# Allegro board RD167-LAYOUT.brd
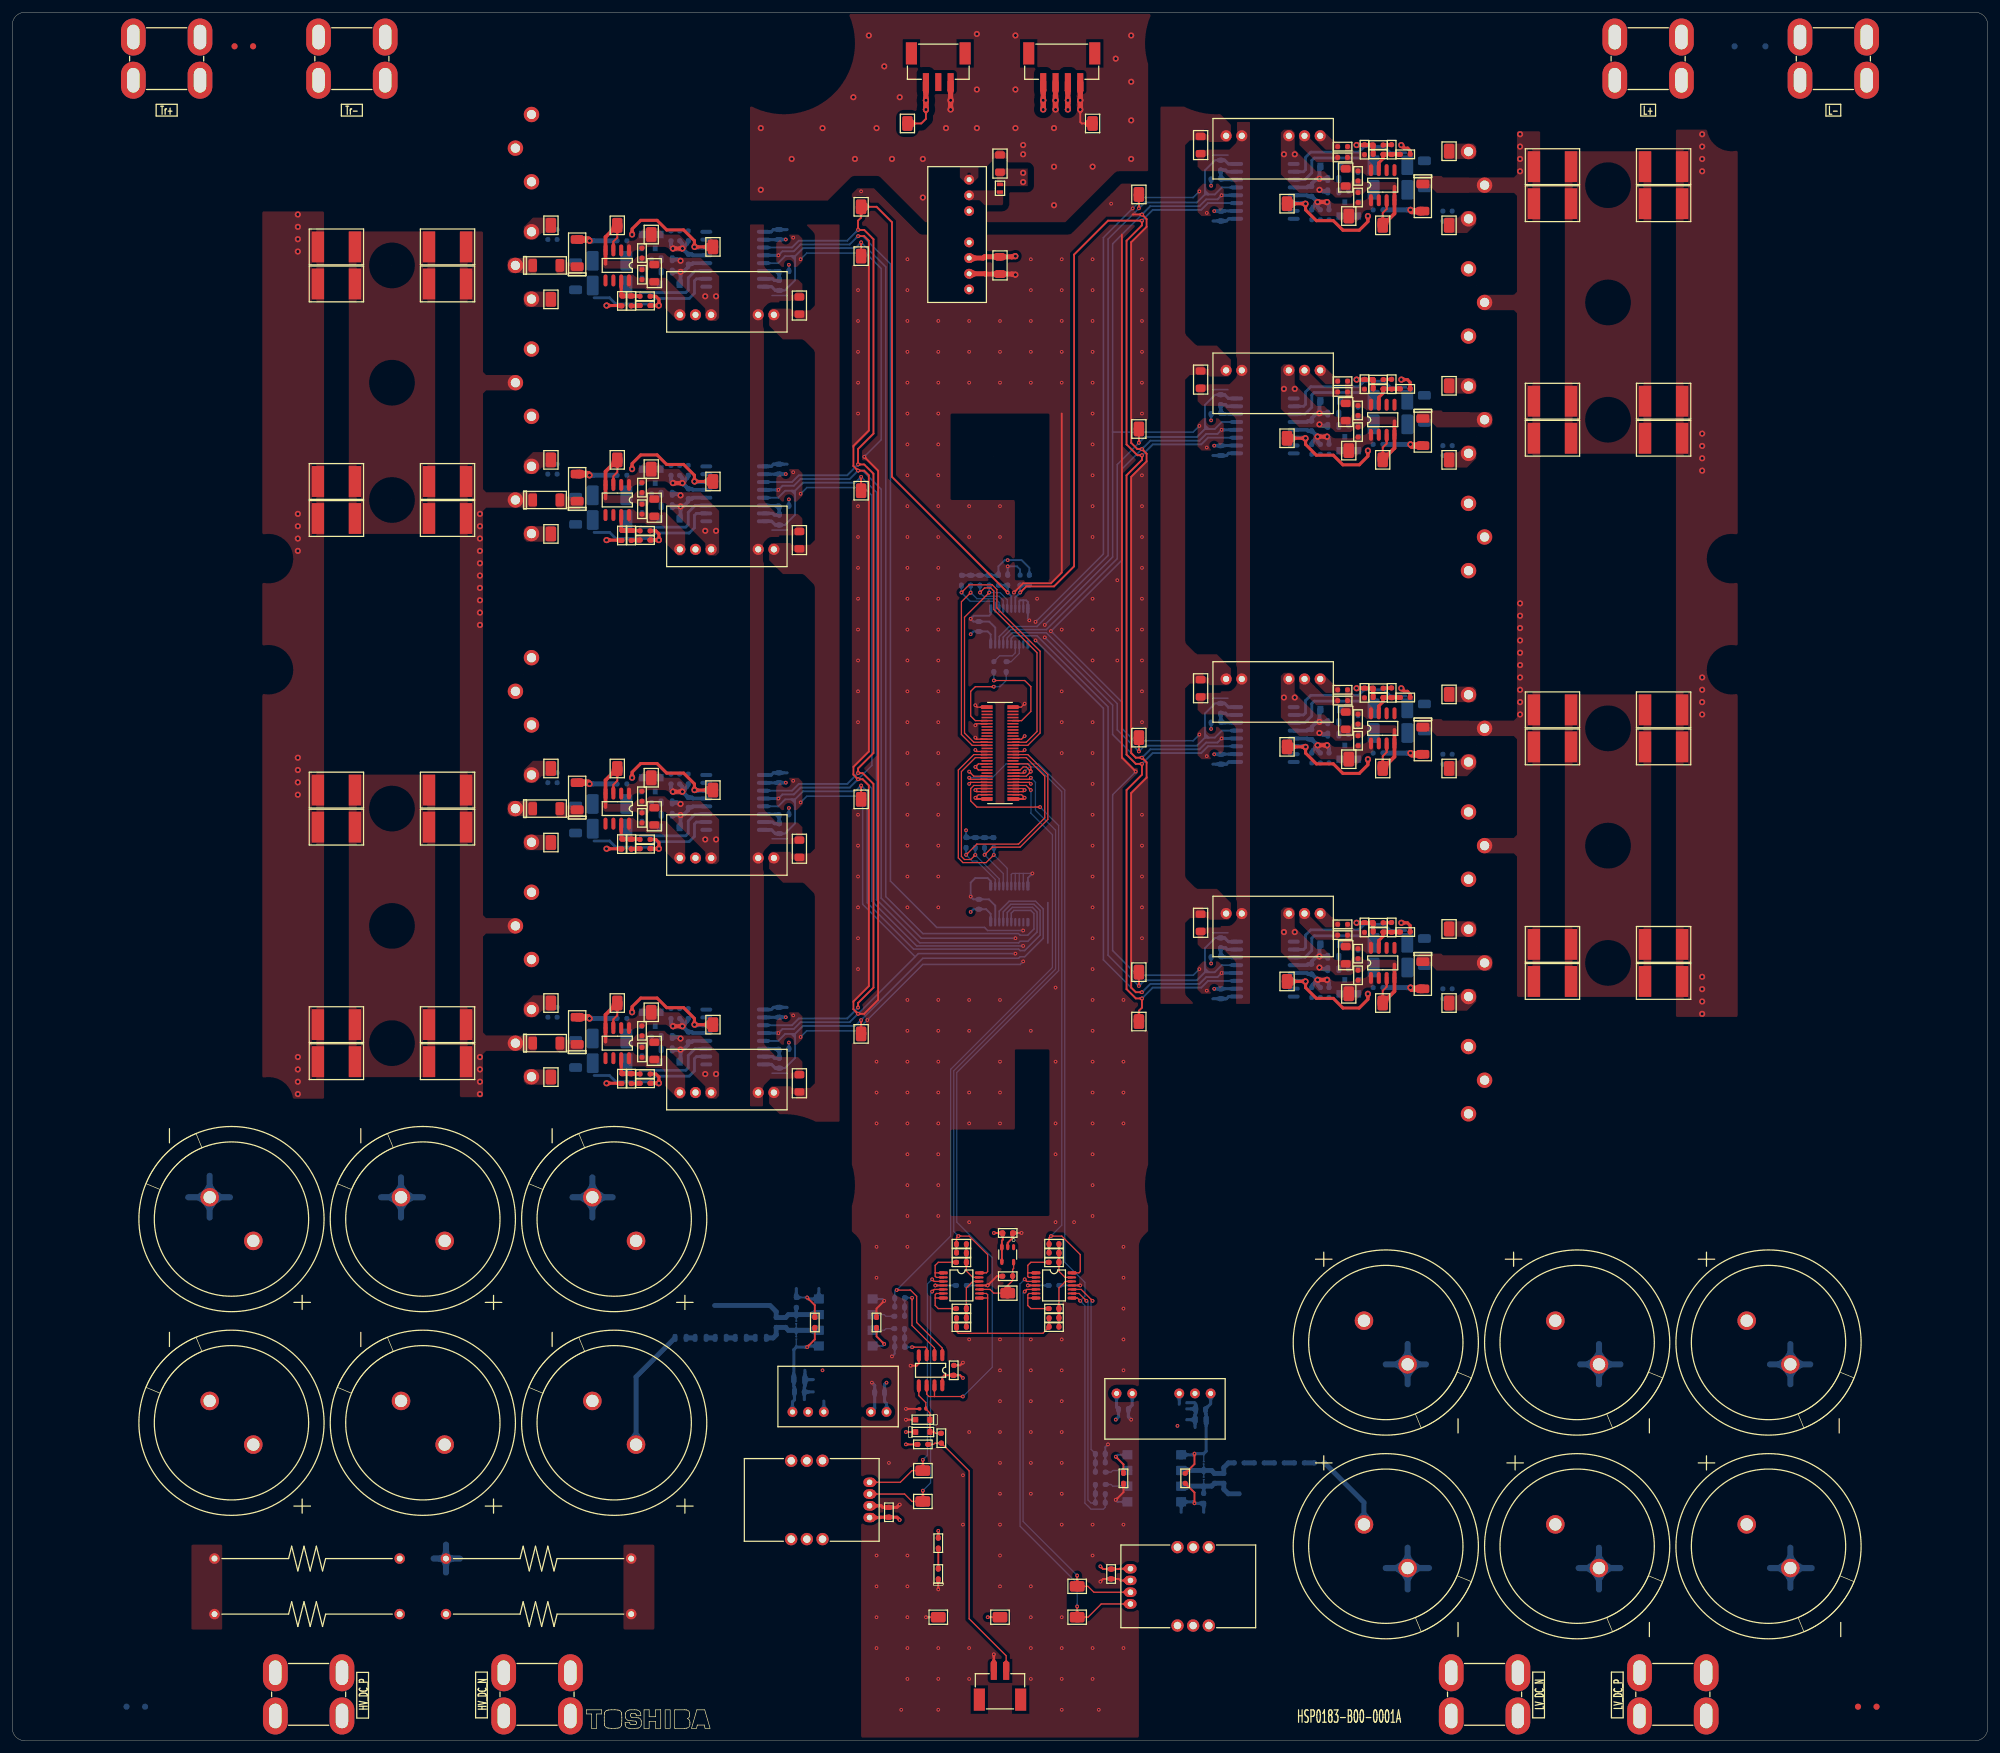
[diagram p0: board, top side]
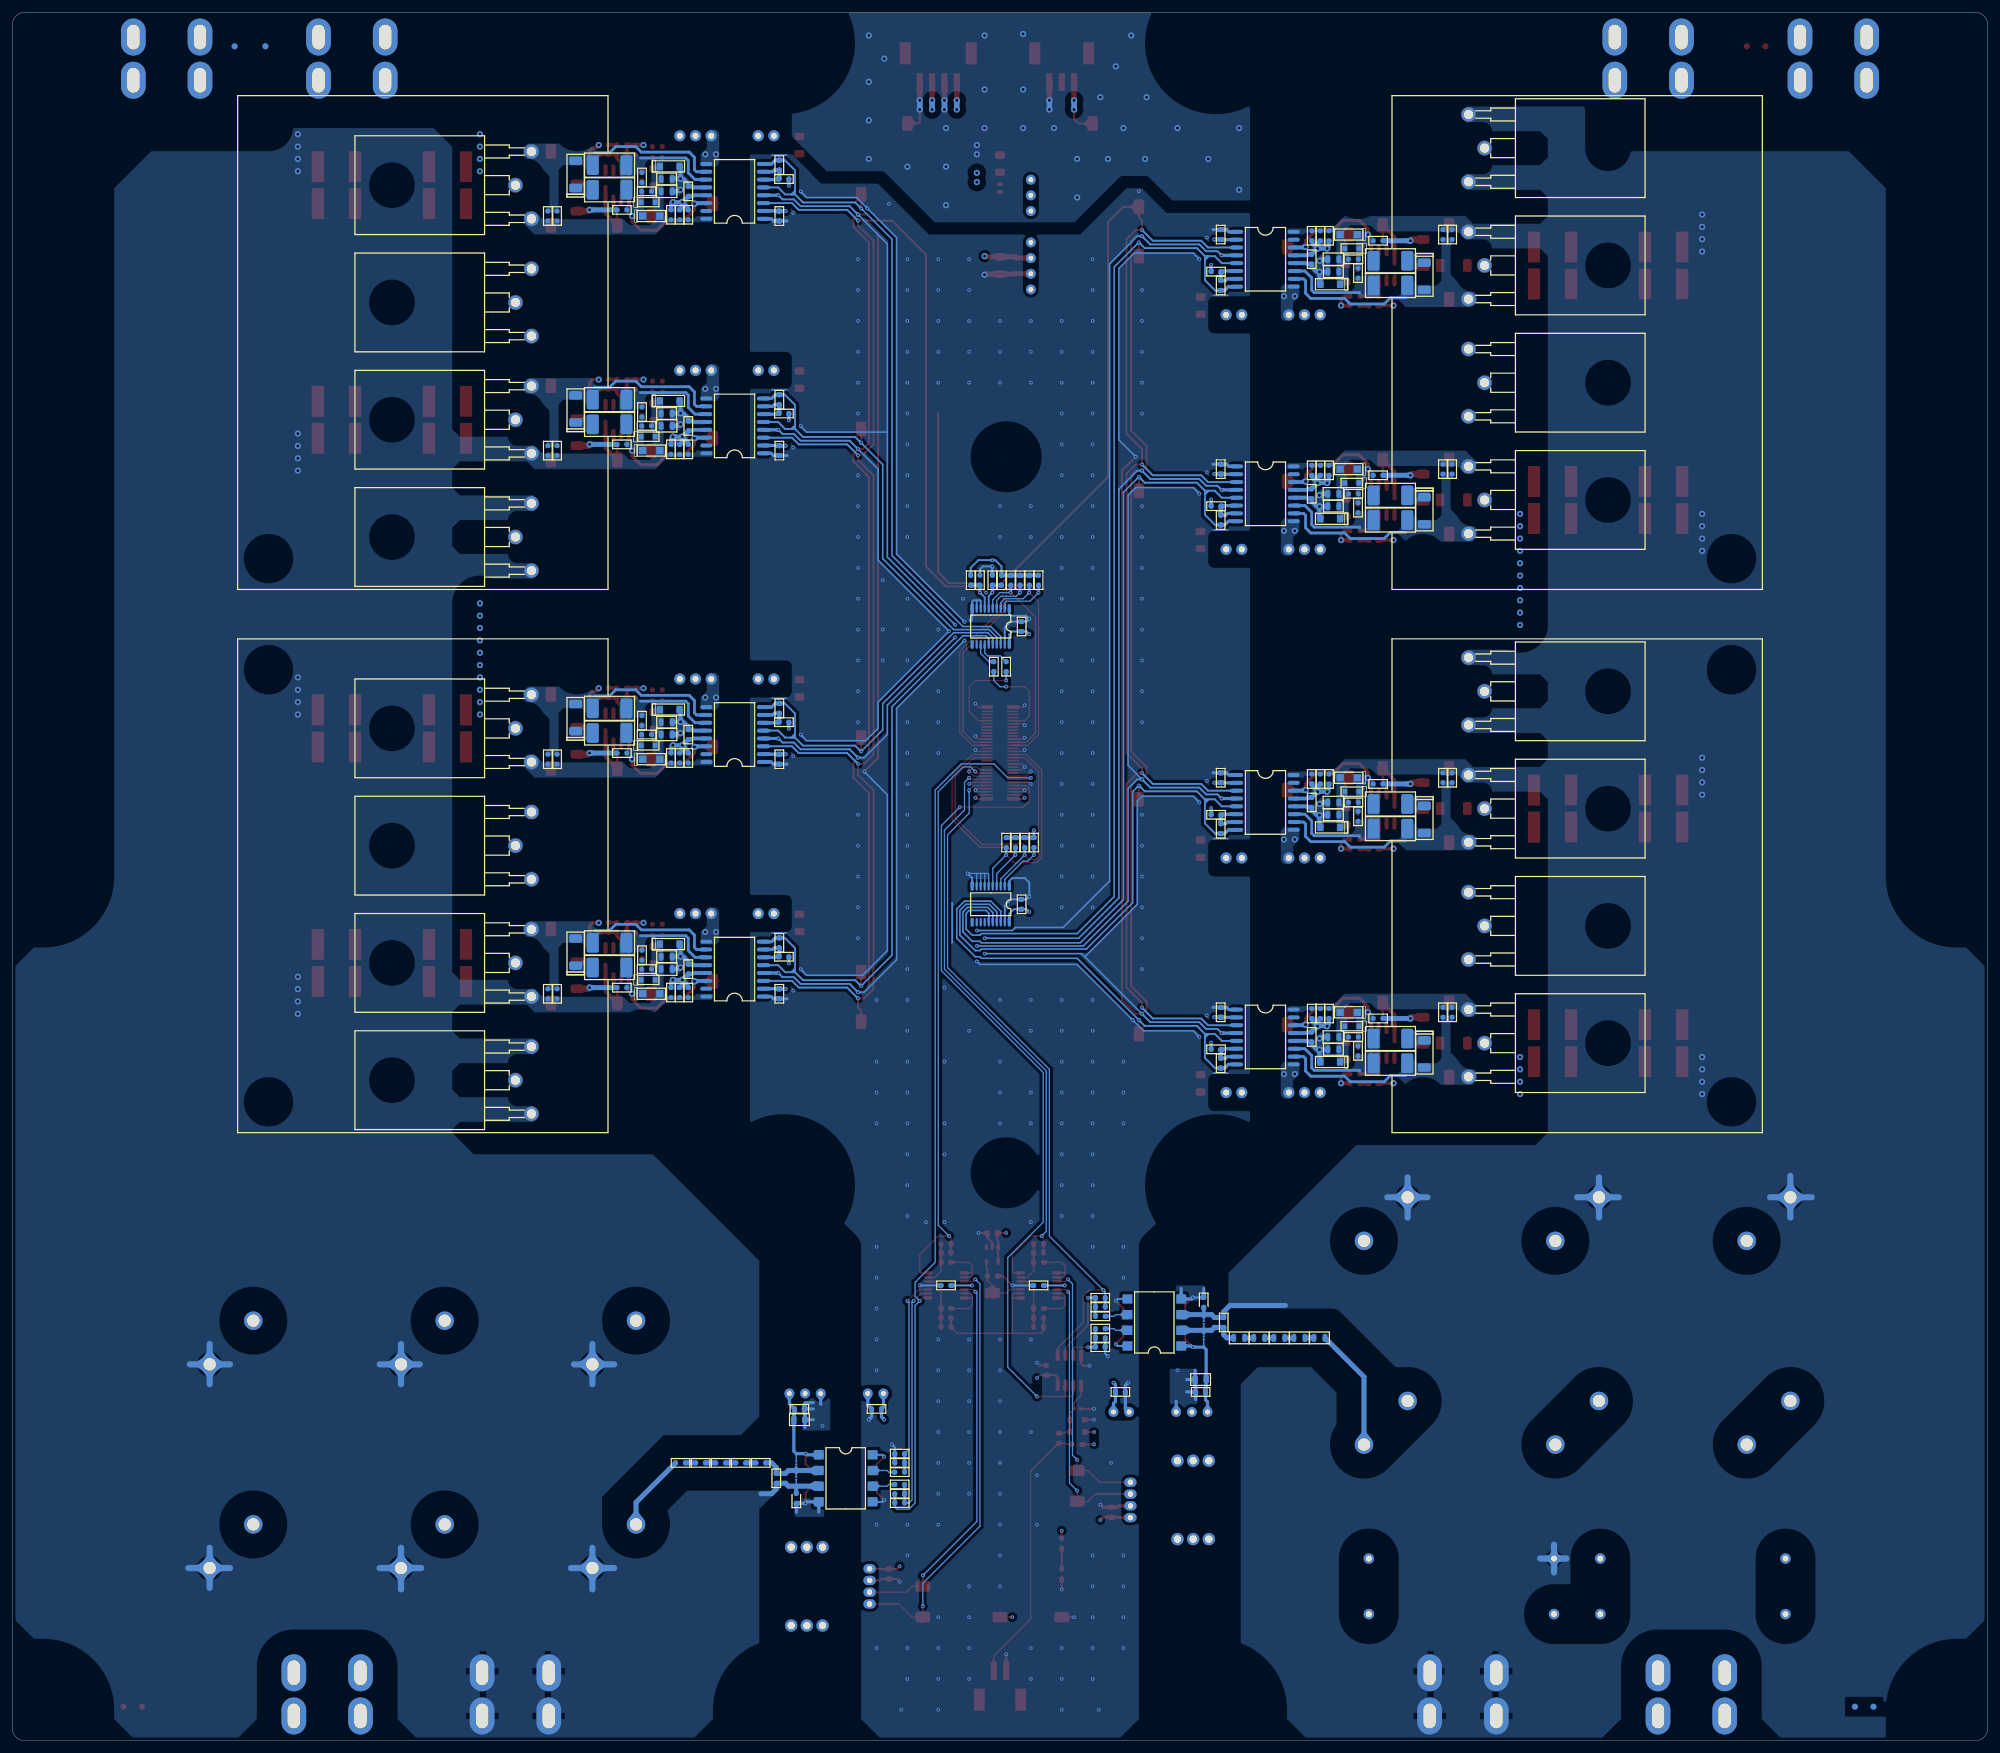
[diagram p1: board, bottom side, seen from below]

Outline 320 x 280 mm; copper layers: TOP, CONDUCTIVE2, CONDUCTIVE3, CONDUCTIVE4, CONDUCTIVE5, BOTTOM. Coordinates in mm from the lower left corner of the outline.
Outline path: 0,278 0.03,278.35 0.12,278.68 0.27,279 0.47,279.29 0.71,279.53 1,279.73 1.32,279.88 1.65,279.97 2,280 318,280 318.35,279.97 318.68,279.88 319,279.73 319.29,279.53 319.53,279.29 319.73,279 319.88,278.68 319.97,278.35 320,278 320,2 319.97,1.65 319.88,1.32 319.73,1 319.53,0.71 319.29,0.47 319,0.27 318.68,0.12 318.35,0.03 318,0 2,0 1.65,0.03 1.32,0.12 1,0.27 0.71,0.47 0.47,0.71 0.27,1 0.12,1.32 0.03,1.65 0,2 0,278

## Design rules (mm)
constraint set DEFAULT: 

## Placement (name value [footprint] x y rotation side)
C1  -  [C_S_1608]  142 37 90 top
C2  -  [C_D_ESMR_VS_30_0X40__1]  35.5 51.5 90 top
C3  -  [C_D_ESMR_VS_30_0X40__1]  66.5 51.5 90 top
C4  -  [C_D_ESMR_VS_30_0X40__1]  97.5 51.5 90 top
C5  -  [C_D_ESMR_VS_30_0X40__1]  35.5 84.5 90 top
C6  -  [C_D_ESMR_VS_30_0X40__1]  66.5 84.5 90 top
C7  -  [C_D_ESMR_VS_30_0X40__1]  97.5 84.5 90 top
C8  -  [C_S_1005]  147.5 53.75 180 top
C10  -  [C_S_1608]  140 67.75 90 top
C11  -  [C_S_1608]  130 67.75 90 top
C12  -  [C_S_1608]  143.75 63.75 0 bottom
C13  -  [C_S_1608]  153.75 73.75 0 bottom
C14  -  [C_S_1608]  125.25 67.75 90 bottom
C15  -  [C_S_1608]  143.75 71.75 0 bottom
C16  -  [C_S_1608]  127.5 56.5 0 bottom
C17  -  [C_S_1608]  140.5 56.5 180 bottom
C18  -  [C_S_1608]  102 115 270 top
C19  -  [C_S_1608]  102.5 108 180 top
C20  -  [C_S_1608]  102 111.5 90 top
C21  -  [C_S_3216_T1_8]  104 111.75 90 top
C22  -  [C_S_3216_T1_8]  127.5 106.5 90 top
C23  -  [C_S_1608]  109.5 117.8 90 bottom
C24  -  [C_S_1608]  109.5 114 270 bottom
C25  -  [C_S_1608]  124.25 118 90 bottom
C26  -  [C_S_1608]  86.75 118 90 bottom
C27  -  [C_S_1608]  102.75 114 0 bottom
C28  -  [C_S_CKG57_6050]  70.5 110 180 top
C29  -  [C_S_CKG57_6050]  70.5 116 180 top
C31  -  [C_S_2012]  106 114 0 bottom
C32  -  [C_S_CKG57_6050]  70.5 148 180 top
C33  -  [C_S_CKG57_6050]  70.5 154 180 top
C34  -  [C_S_CKG57_6050]  52.5 110 180 top
C35  -  [C_S_CKG57_6050]  52.5 116 180 top
C36  -  [C_S_CKG57_6050]  52.5 148 180 top
C37  -  [C_S_CKG57_6050]  52.5 154 180 top
C38  -  [C_S_1608]  102 153 270 top
C39  -  [C_S_1608]  102.5 146 180 top
C40  -  [C_S_1608]  102 149.5 90 top
C41  -  [C_S_3216_T1_8]  104 149.75 90 top
C42  -  [C_S_3216_T1_8]  127.5 144.5 90 top
C43  -  [C_S_1608]  109.5 155.8 90 bottom
C44  -  [C_S_1608]  109.5 152 270 bottom
C45  -  [C_S_1608]  124.25 156 90 bottom
C46  -  [C_S_1608]  86.75 156 90 bottom
C47  -  [C_S_1608]  102.75 152 0 bottom
C49  -  [C_S_2012]  106 152 0 bottom
C50  -  [C_S_1608]  102 203 270 top
C51  -  [C_S_1608]  102.5 196 180 top
C52  -  [C_S_1608]  102 199.5 90 top
C53  -  [C_S_3216_T1_8]  104 199.75 90 top
C54  -  [C_S_3216_T1_8]  127.5 194.5 90 top
C55  -  [C_S_1608]  109.5 205.8 90 bottom
C56  -  [C_S_1608]  109.5 202 270 bottom
C57  -  [C_S_1608]  124.25 206 90 bottom
C58  -  [C_S_1608]  86.75 206 90 bottom
C59  -  [C_S_1608]  102.75 202 0 bottom
C61  -  [C_S_2012]  106 202 0 bottom
C62  -  [C_S_CKG57_6050]  70.5 198 180 top
C63  -  [C_S_CKG57_6050]  70.5 204 180 top
C64  -  [C_S_CKG57_6050]  70.5 236 180 top
C65  -  [C_S_CKG57_6050]  70.5 242 180 top
C66  -  [C_S_CKG57_6050]  52.5 198 180 top
C67  -  [C_S_CKG57_6050]  52.5 204 180 top
C68  -  [C_S_CKG57_6050]  52.5 236 180 top
C69  -  [C_S_CKG57_6050]  52.5 242 180 top
C70  -  [C_S_1608]  102 241 270 top
C71  -  [C_S_1608]  102.5 234 180 top
C72  -  [C_S_1608]  102 237.5 90 top
C73  -  [C_S_3216_T1_8]  104 237.75 90 top
C74  -  [C_S_3216_T1_8]  127.5 232.5 90 top
C75  -  [C_S_1608]  109.5 243.8 90 bottom
C76  -  [C_S_1608]  109.5 240 270 bottom
C77  -  [C_S_1608]  124.25 244 90 bottom
C78  -  [C_S_1608]  86.75 244 90 bottom
C79  -  [C_S_1608]  102.75 240 0 bottom
C81  -  [C_S_2012]  106 240 0 bottom
C82  -  [C_S_3216_T1_8]  192.5 258.5 270 top
C83  -  [C_S_3216_T1_8]  216 253.25 270 top
C84  -  [C_S_1608]  218 253.5 270 top
C85  -  [C_S_1608]  221.25 257 0 top
C86  -  [C_S_1608]  218 250 90 top
C87  -  [C_S_1608]  195.75 247 270 bottom
C88  -  [C_S_1608]  210.5 251 90 bottom
C89  -  [C_S_1608]  210.5 247.2 270 bottom
C90  -  [C_S_1608]  217.25 251 180 bottom
C91  -  [C_S_1608]  233.25 247 270 bottom
C92  -  [C_S_2012]  214 251 180 bottom
C94  -  [C_S_CKG57_6050]  249.5 255 0 top
C95  -  [C_S_CKG57_6050]  249.5 249 0 top
C96  -  [C_S_CKG57_6050]  249.5 217 0 top
C97  -  [C_S_CKG57_6050]  249.5 211 0 top
C98  -  [C_S_CKG57_6050]  267.5 255 0 top
C99  -  [C_S_CKG57_6050]  267.5 249 0 top
C100  -  [C_S_CKG57_6050]  267.5 217 0 top
C101  -  [C_S_CKG57_6050]  267.5 211 0 top
C102  -  [C_S_3216_T1_8]  192.5 220.5 270 top
C103  -  [C_S_3216_T1_8]  216 215.25 270 top
C104  -  [C_S_1608]  218 215.5 270 top
C105  -  [C_S_1608]  221.25 219 0 top
C106  -  [C_S_1608]  218 212 90 top
C107  -  [C_S_1608]  195.75 209 270 bottom
C108  -  [C_S_1608]  210.5 213 90 bottom
C109  -  [C_S_1608]  210.5 209.2 270 bottom
C110  -  [C_S_1608]  217.25 213 180 bottom
C111  -  [C_S_1608]  233.25 209 270 bottom
C112  -  [C_S_2012]  214 213 180 bottom
C114  -  [C_S_3216_T1_8]  192.5 170.5 270 top
C115  -  [C_S_3216_T1_8]  216 165.25 270 top
C116  -  [C_S_1608]  218 165.5 270 top
C117  -  [C_S_1608]  221.25 169 0 top
C118  -  [C_S_1608]  218 162 90 top
C119  -  [C_S_1608]  195.75 159 270 bottom
C120  -  [C_S_1608]  210.5 163 90 bottom
C121  -  [C_S_1608]  210.5 159.2 270 bottom
C122  -  [C_S_1608]  217.25 163 180 bottom
C123  -  [C_S_1608]  233.25 159 270 bottom
C124  -  [C_S_2012]  214 163 180 bottom
C126  -  [C_S_CKG57_6050]  249.5 167 0 top
C127  -  [C_S_CKG57_6050]  249.5 161 0 top
C128  -  [C_S_CKG57_6050]  249.5 129 0 top
C129  -  [C_S_CKG57_6050]  249.5 123 0 top
C130  -  [C_S_CKG57_6050]  267.5 167 0 top
C131  -  [C_S_CKG57_6050]  267.5 161 0 top
C132  -  [C_S_CKG57_6050]  267.5 129 0 top
C133  -  [C_S_CKG57_6050]  267.5 123 0 top
C134  -  [C_S_3216_T1_8]  192.5 132.5 270 top
C135  -  [C_S_3216_T1_8]  216 127.25 270 top
C136  -  [C_S_1608]  218 127.5 270 top
C137  -  [C_S_1608]  221.25 131 0 top
C138  -  [C_S_1608]  218 124 90 top
C139  -  [C_S_1608]  195.75 121 270 bottom
C140  -  [C_S_1608]  210.5 125 90 bottom
C141  -  [C_S_1608]  210.5 121.2 270 bottom
C142  -  [C_S_1608]  217.25 125 180 bottom
C143  -  [C_S_1608]  233.25 121 270 bottom
C144  -  [C_S_2012]  214 125 180 bottom
C146  -  [C_S_1608]  178 27 270 top
C147  -  [C_D_ESMR_VS_30_0X40__1]  284.5 64.5 270 top
C148  -  [C_D_ESMR_VS_30_0X40__1]  253.5 64.5 270 top
C149  -  [C_D_ESMR_VS_30_0X40__1]  222.5 64.5 270 top
C150  -  [C_D_ESMR_VS_30_0X40__1]  284.5 31.5 270 top
C151  -  [C_D_ESMR_VS_30_0X40__1]  253.5 31.5 270 top
C152  -  [C_D_ESMR_VS_30_0X40__1]  222.5 31.5 270 top
C153  -  [C_S_1608]  180 42.5 270 top
C154  -  [C_S_1608]  176.25 38.5 180 bottom
C155  -  [C_S_1608]  190 42.5 270 top
C157  -  [C_S_1608]  194.75 42.5 270 bottom
C158  -  [C_S_1608]  152.5 60 90 top
C159  -  [C_S_1608]  176.25 46.5 180 bottom
C160  -  [C_S_1608]  180 53.75 0 bottom
C161  -  [C_S_1608]  192.5 53.75 180 bottom
C162  -  [C_S_3216_T1_8]  160 255.5 90 top
C163  -  [C_S_3216_T1_8]  160 239 270 top
C164  -  [C_S_1608]  156.5 135.5 90 bottom
C165  -  [C_S_1608]  156.5 180.5 90 bottom
C166  -  [C_S_1608]  163.25 188 90 bottom
C167  -  [C_S_1608]  161.25 188 90 bottom
C168  -  [C_S_1608]  153.75 80.5 180 top
C170  -  [C_S_1608]  153.75 67 180 top
C171  -  [C_S_1608]  168.75 80.5 180 top
C172  -  [C_S_1608]  168.75 73.75 0 bottom
C173  -  [C_S_1608]  168.75 67 180 top
C174  -  [C_S_1608]  161.25 82.25 0 top
C175  -  [C_S_1608]  161.25 75.25 180 top
CN1  -  [CN_S_BM02B_PASS_TFT__1]  160 8 0 top
CN2  -  [CN_S_BM03B_PASS_TFT__1]  150 272 180 top
CN3  -  [CN_S_BM04B_PASS_TFT__1]  170 272 180 top
CN4  -  [CN_S_WR_60S_VFH05_N1]  160 160 90 top
CT1  -  [CT_D_F02PXXXS05L]  129.5 39 180 top
CT2  -  [CT_D_F02PXXXS05L]  190.5 25 0 top
D2  -  [D_S_1_1E1A_USC_AK]  147.5 50 180 top
D3  -  [D_S_1_1E1A_USC_AK]  147.5 52 0 top
D5  -  [D_S_SOD_962_SL2_AK]  127 65.25 90 bottom
D6  -  [D_S_SOD_962_SL2_AK]  127 67.75 90 bottom
D7  -  [D_S_M_FLAT_3_4E1A_AK]  86.5 113 180 top
D8  -  [D_S_M_FLAT_3_4E1A_AK]  91.5 115 270 top
D9  -  [D_S_M_FLAT_3_4E1A_AK]  91.25 111.25 90 bottom
D10  -  [D_S_1_1E1A_USC_AK]  103 115.75 180 bottom
D11  -  [D_S_FLAT_3_2A1S]  103.5 118 180 bottom
D12  -  [D_S_SOD_123_PMDU_AK]  106.5 109.95 180 bottom
D13  -  [D_S_M_FLAT_3_4E1A_AK]  86.5 151 180 top
D14  -  [D_S_M_FLAT_3_4E1A_AK]  91.5 153 270 top
D15  -  [D_S_M_FLAT_3_4E1A_AK]  91.25 149.25 90 bottom
D16  -  [D_S_1_1E1A_USC_AK]  103 153.75 180 bottom
D17  -  [D_S_FLAT_3_2A1S]  103.5 156 180 bottom
D18  -  [D_S_SOD_123_PMDU_AK]  106.5 147.95 180 bottom
D19  -  [D_S_M_FLAT_3_4E1A_AK]  86.5 201 180 top
D20  -  [D_S_M_FLAT_3_4E1A_AK]  91.5 203 270 top
D21  -  [D_S_M_FLAT_3_4E1A_AK]  91.25 199.25 90 bottom
D22  -  [D_S_1_1E1A_USC_AK]  103 203.75 180 bottom
D23  -  [D_S_FLAT_3_2A1S]  103.5 206 180 bottom
D24  -  [D_S_SOD_123_PMDU_AK]  106.5 197.95 180 bottom
D25  -  [D_S_M_FLAT_3_4E1A_AK]  86.5 239 180 top
D26  -  [D_S_M_FLAT_3_4E1A_AK]  91.5 241 270 top
D27  -  [D_S_M_FLAT_3_4E1A_AK]  91.25 237.25 90 bottom
D28  -  [D_S_1_1E1A_USC_AK]  103 241.75 180 bottom
D29  -  [D_S_FLAT_3_2A1S]  103.5 244 180 bottom
D30  -  [D_S_SOD_123_PMDU_AK]  106.5 235.95 180 bottom
D31  -  [D_S_M_FLAT_3_4E1A_AK]  228.5 250 90 top
D33  -  [D_S_M_FLAT_3_4E1A_AK]  228.75 253.75 270 bottom
D34  -  [D_S_FLAT_3_2A1S]  216.5 247 0 bottom
D35  -  [D_S_1_1E1A_USC_AK]  217 249.25 0 bottom
D36  -  [D_S_SOD_123_PMDU_AK]  213.5 255.05 0 bottom
D37  -  [D_S_M_FLAT_3_4E1A_AK]  228.5 212 90 top
D39  -  [D_S_M_FLAT_3_4E1A_AK]  228.75 215.75 270 bottom
D40  -  [D_S_FLAT_3_2A1S]  216.5 209 0 bottom
D41  -  [D_S_1_1E1A_USC_AK]  217 211.25 0 bottom
D42  -  [D_S_SOD_123_PMDU_AK]  213.5 217.05 0 bottom
D43  -  [D_S_M_FLAT_3_4E1A_AK]  228.5 162 90 top
D45  -  [D_S_M_FLAT_3_4E1A_AK]  228.75 165.75 270 bottom
D46  -  [D_S_FLAT_3_2A1S]  216.5 159 0 bottom
D47  -  [D_S_1_1E1A_USC_AK]  217 161.25 0 bottom
D48  -  [D_S_SOD_123_PMDU_AK]  213.5 167.05 0 bottom
D49  -  [D_S_M_FLAT_3_4E1A_AK]  228.5 124 90 top
D51  -  [D_S_M_FLAT_3_4E1A_AK]  228.75 127.75 270 bottom
D52  -  [D_S_FLAT_3_2A1S]  216.5 121 0 bottom
D53  -  [D_S_1_1E1A_USC_AK]  217 123.25 0 bottom
D54  -  [D_S_SOD_123_PMDU_AK]  213.5 129.05 0 bottom
D56  -  [D_S_SOD_962_SL2_AK]  193 45 270 bottom
D58  -  [D_S_SOD_962_SL2_AK]  193 42.5 270 bottom
D59  -  [D_D_TO_247_3_AK_REVE_1]  81.5 132 270 bottom
D60  -  [D_D_TO_247_3_AK_REVE_1]  81.5 170 270 bottom
D61  -  [D_D_TO_247_3_AK_REVE_1]  81.5 220 270 bottom
D62  -  [D_D_TO_247_3_AK_REVE_1]  81.5 258 270 bottom
D63  -  [D_D_TO_247_3_AK_REVE_1]  238.5 233 90 bottom
D64  -  [D_D_TO_247_3_AK_REVE_1]  238.5 195 90 bottom
D65  -  [D_D_TO_247_3_AK_REVE_1]  238.5 145 90 bottom
D66  -  [D_D_TO_247_3_AK_REVE_1]  238.5 107 90 bottom
IC1  -  [IC_SOP14_0_65_PW]  153.75 73.75 270 top
IC2  -  [IC_SOP8_2_54_11_10C4_1]  135 67.75 90 bottom
IC3  -  [IC_SOP8_1_27_D]  98 113 180 top
IC4  -  [IC_SOP16_1_27_11_10M_1]  117 114 270 bottom
IC5  -  [IC_SOP8_1_27_D]  98 151 180 top
IC6  -  [IC_SOP16_1_27_11_10M_1]  117 152 270 bottom
IC7  -  [IC_SOP8_1_27_D]  98 201 180 top
IC8  -  [IC_SOP16_1_27_11_10M_1]  117 202 270 bottom
IC9  -  [IC_SOP8_1_27_D]  98 239 180 top
IC10  -  [IC_SOP16_1_27_11_10M_1]  117 240 270 bottom
IC11  -  [IC_SOP8_1_27_D]  222 252 0 top
IC12  -  [IC_SOP16_1_27_11_10M_1]  203 251 90 bottom
IC13  -  [IC_SOP8_1_27_D]  222 214 0 top
IC14  -  [IC_SOP16_1_27_11_10M_1]  203 213 90 bottom
IC15  -  [IC_SOP8_1_27_D]  222 164 0 top
IC16  -  [IC_SOP16_1_27_11_10M_1]  203 163 90 bottom
IC17  -  [IC_SOP8_1_27_D]  222 126 0 top
IC18  -  [IC_SOP16_1_27_11_10M_1]  203 125 90 bottom
IC19  -  [IC_SOP8_1_27_D]  148.75 60 180 top
IC20  -  [IC_SOP8_2_54_11_10C4_1]  185 42.5 270 bottom
IC21  -  [IC_SOP20_0_65_FT]  161.5 135.5 0 bottom
IC22  -  [IC_SOP20_0_65_FT]  161.5 180.5 0 bottom
IC23  -  [IC_SOP5_0_95_DDC]  161.25 78.75 90 top
IC24  -  [IC_SOP14_0_65_PW]  168.75 73.75 270 top
L1  -  [L_S_MBKK1608]  160 251.5 270 top
LED1  -  [LED_S_1608_AK]  150 27 270 top
NOREF  -  [unnamed]  41.5 261.5 90 top
NOREF#2  -  [unnamed]  91.5 261.5 90 top
NOREF#3  -  [unnamed]  228.5 261.5 0 top
NOREF#4  -  [unnamed]  41.5 103.5 90 top
NOREF#5  -  [unnamed]  228.5 191.5 0 top
NOREF#6  -  [unnamed]  278.5 191.5 0 top
NOREF#7  -  [#2]  93 2 0 top
NOREF#8  -  [#2]  5 5 0 top
NOREF#9  -  [unnamed#3]  160 170 270 top
NOREF#10  -  [#2]  125 90 0 top
NOREF#11  -  [#2]  195 5 0 top
NOREF#12  -  [unnamed]  91.5 191.5 0 top
NOREF#13  -  [unnamed]  41.5 173.5 0 top
NOREF#14  -  [unnamed]  278.5 261.5 0 top
NOREF#15  -  [unnamed]  91.5 103.5 90 top
NOREF#16  -  [unnamed]  228.5 103.5 270 top
NOREF#17  -  [unnamed]  41.5 191.5 0 top
NOREF#18  -  [#2]  5 140 0 top
NOREF#19  -  [unnamed]  278.5 103.5 270 top
NOREF#20  -  [#2]  125 275 0 top
NOREF#21  -  [#2]  315 275 270 top
NOREF#22  -  [unnamed]  299 5.5 0 top
NOREF#23  -  [unnamed]  91.5 173.5 0 top
NOREF#24  -  [#2]  125 5 0 top
NOREF#25  -  [unnamed]  36 274.5 0 top
NOREF#26  -  [unnamed]  228.5 173.5 0 top
NOREF#27  -  [#2]  315 140 0 top
NOREF#28  -  [#2]  5 275 0 top
NOREF#29  -  [unnamed]  39 274.5 0 top
NOREF#30  -  [#2]  195 90 0 top
NOREF#31  -  [unnamed]  278.5 173.5 0 top
NOREF#32  -  [#2]  195 275 0 top
NOREF#33  -  [unnamed]  302 5.5 0 top
NOREF#34  -  [#2]  315 5 0 top
NOREF#35  -  [unnamed]  21.5 5.5 180 bottom
NOREF#36  -  [unnamed]  284 274.5 90 bottom
NOREF#37  -  [unnamed]  18.5 5.5 180 bottom
NOREF#38  -  [unnamed]  279 274.5 90 bottom
PS1  -  [IC_D_RXXPXX]  134 53.25 180 top
PS2  -  [PS_D_S_2WR2_MORNSUN]  115.75 105 180 top
PS3  -  [PS_D_S_2WR2_MORNSUN]  115.75 143 180 top
PS4  -  [PS_D_S_2WR2_MORNSUN]  115.75 193 180 top
PS5  -  [PS_D_S_2WR2_MORNSUN]  115.75 231 180 top
PS6  -  [PS_D_S_2WR2_MORNSUN]  204.25 260 0 top
PS7  -  [PS_D_S_2WR2_MORNSUN]  204.25 222 0 top
PS8  -  [PS_D_S_2WR2_MORNSUN]  204.25 172 0 top
PS9  -  [PS_D_S_2WR2_MORNSUN]  204.25 134 0 top
PS10  -  [IC_D_RXXPXX]  186.5 56.25 0 top
PS11  -  [IC_D_MGFS10_COSEL]  155 244 270 top
Q1  -  [Q_D_TO_247_3_GDS_SP__1]  81.5 113 270 bottom
Q2  -  [Q_D_TO_247_3_GDS_SP__1]  81.5 151 270 bottom
Q3  -  [Q_D_TO_247_3_GDS_SP__1]  81.5 201 270 bottom
Q4  -  [Q_D_TO_247_3_GDS_SP__1]  81.5 239 270 bottom
Q5  -  [Q_D_TO_247_3_GDS_SP__1]  238.5 252 90 bottom
Q6  -  [Q_D_TO_247_3_GDS_SP__1]  238.5 214 90 bottom
Q7  -  [Q_D_TO_247_3_GDS_SP__1]  238.5 164 90 bottom
Q8  -  [Q_D_TO_247_3_GDS_SP__1]  238.5 126 90 bottom
R1  -  [R_D_ROX5S]  47.75 29.5 180 top
R2  -  [R_D_ROX5S]  47.75 20.5 0 top
R3  -  [R_S_1608]  147.5 48 0 top
R4  -  [R_D_ROX5S]  85.25 20.5 0 top
R5  -  [R_S_1608]  150.5 49 270 top
R7  -  [R_D_ROX5S]  85.25 29.5 180 top
R8  -  [R_S_1608]  143.75 65.25 0 bottom
R9  -  [R_S_1608]  143.75 66.75 0 bottom
R10  -  [R_S_2012]  108.25 65.25 0 bottom
R11  -  [R_S_2012]  111.5 65.25 0 bottom
R12  -  [R_S_2012]  114.75 65.25 0 bottom
R13  -  [R_S_2012]  118 65.25 0 bottom
R14  -  [R_S_2012]  121.25 65.25 0 bottom
R15  -  [R_S_1608]  123.75 67.75 90 bottom
R16  -  [R_S_1608]  143.75 68.75 0 bottom
R17  -  [R_S_1608]  127 71 90 bottom
R18  -  [R_S_1608]  143.75 70.25 0 bottom
R19  -  [R_S_2012]  127.5 58.5 0 bottom
R20  -  [R_S_1608]  100.25 107.25 90 top
R21  -  [R_S_1608]  102.5 106.5 180 top
R22  -  [R_S_1608]  98.75 107.25 270 top
R23  -  [R_S_1608]  125 112 180 bottom
R24  -  [R_S_1608]  98.75 117 180 bottom
R25  -  [R_S_1608]  102 111.75 270 bottom
R26  -  [R_S_6432]  96.75 113.75 0 bottom
R27  -  [R_S_6432]  96.75 109.75 180 bottom
R28  -  [R_S_1608]  124.25 109.75 270 bottom
R29  -  [R_S_1608]  88.25 118 90 bottom
R30  -  [R_S_1608]  108.1 117.8 90 bottom
R31  -  [R_S_1608]  106.7 117.8 90 bottom
R32  -  [R_S_1608]  102.5 144.5 180 top
R33  -  [R_S_1608]  98.75 145.25 270 top
R34  -  [R_S_1608]  100.25 145.25 90 top
R35  -  [R_S_1608]  125 150 180 bottom
R36  -  [R_S_1608]  98.75 155 180 bottom
R37  -  [R_S_1608]  102 149.75 270 bottom
R38  -  [R_S_6432]  96.75 151.75 0 bottom
R39  -  [R_S_6432]  96.75 147.75 180 bottom
R40  -  [R_S_1608]  124.25 147.75 270 bottom
R41  -  [R_S_1608]  88.25 156 90 bottom
R42  -  [R_S_1608]  108.1 155.8 90 bottom
R43  -  [R_S_1608]  106.7 155.8 90 bottom
R44  -  [R_S_1608]  100.25 195.25 90 top
R45  -  [R_S_1608]  102.5 194.5 180 top
R46  -  [R_S_1608]  98.75 195.25 270 top
R47  -  [R_S_1608]  125 200 180 bottom
R48  -  [R_S_1608]  98.75 205 180 bottom
R49  -  [R_S_1608]  102 199.75 270 bottom
R50  -  [R_S_6432]  96.75 201.75 0 bottom
R51  -  [R_S_6432]  96.75 197.75 180 bottom
R52  -  [R_S_1608]  124.25 197.75 270 bottom
R53  -  [R_S_1608]  88.25 206 90 bottom
R54  -  [R_S_1608]  108.1 205.8 90 bottom
R55  -  [R_S_1608]  106.7 205.8 90 bottom
R56  -  [R_S_1608]  100.25 233.25 90 top
R57  -  [R_S_1608]  102.5 232.5 180 top
R58  -  [R_S_1608]  98.75 233.25 270 top
R59  -  [R_S_1608]  125 238 180 bottom
R60  -  [R_S_1608]  98.75 243 180 bottom
R61  -  [R_S_1608]  102 237.75 270 bottom
R62  -  [R_S_6432]  96.75 239.75 0 bottom
R63  -  [R_S_6432]  96.75 235.75 180 bottom
R64  -  [R_S_1608]  124.25 235.75 270 bottom
R65  -  [R_S_1608]  88.25 244 90 bottom
R66  -  [R_S_1608]  108.1 243.8 90 bottom
R67  -  [R_S_1608]  106.7 243.8 90 bottom
R68  -  [R_S_1608]  221.25 258.5 0 top
R69  -  [R_S_1608]  223.45 257.75 270 top
R70  -  [R_S_1608]  225.65 257 0 top
R71  -  [R_S_1608]  195 253 0 bottom
R72  -  [R_S_1608]  221.25 248 180 bottom
R73  -  [R_S_1608]  218 253.25 90 bottom
R74  -  [R_S_6432]  223.25 251.25 180 bottom
R75  -  [R_S_1608]  195.75 255.25 90 bottom
R76  -  [R_S_6432]  223.25 255.25 180 bottom
R77  -  [R_S_1608]  211.9 247.2 270 bottom
R78  -  [R_S_1608]  213.3 247.2 270 bottom
R79  -  [R_S_1608]  231.75 247 270 bottom
R80  -  [R_S_1608]  221.25 220.5 0 top
R81  -  [R_S_1608]  223.45 219.75 270 top
R82  -  [R_S_1608]  225.65 219 0 top
R83  -  [R_S_1608]  195 215 0 bottom
R84  -  [R_S_1608]  221.25 210 180 bottom
R85  -  [R_S_1608]  218 215.25 90 bottom
R86  -  [R_S_6432]  223.25 213.25 180 bottom
R87  -  [R_S_1608]  195.75 217.25 90 bottom
R88  -  [R_S_6432]  223.25 217.25 180 bottom
R89  -  [R_S_1608]  211.9 209.2 270 bottom
R90  -  [R_S_1608]  213.3 209.2 270 bottom
R91  -  [R_S_1608]  231.75 209 270 bottom
R92  -  [R_S_1608]  221.25 170.5 0 top
R93  -  [R_S_1608]  223.45 169.75 270 top
R94  -  [R_S_1608]  225.65 169 0 top
R95  -  [R_S_1608]  195 165 0 bottom
R96  -  [R_S_1608]  221.25 160 180 bottom
R97  -  [R_S_1608]  218 165.25 90 bottom
R98  -  [R_S_6432]  223.25 163.25 180 bottom
R99  -  [R_S_1608]  195.75 167.25 90 bottom
R100  -  [R_S_6432]  223.25 167.25 180 bottom
R101  -  [R_S_1608]  211.9 159.2 270 bottom
R102  -  [R_S_1608]  213.3 159.2 270 bottom
R103  -  [R_S_1608]  231.75 159 270 bottom
R104  -  [R_S_1608]  221.25 132.5 0 top
R105  -  [R_S_1608]  223.45 131.75 270 top
R106  -  [R_S_1608]  225.65 131 0 top
R107  -  [R_S_1608]  195 127 0 bottom
R108  -  [R_S_1608]  221.25 122 180 bottom
R109  -  [R_S_1608]  218 127.25 90 bottom
R110  -  [R_S_6432]  223.25 125.25 180 bottom
R111  -  [R_S_1608]  195.75 129.25 90 bottom
R112  -  [R_S_6432]  223.25 129.25 180 bottom
R113  -  [R_S_1608]  211.9 121.2 270 bottom
R114  -  [R_S_1608]  213.3 121.2 270 bottom
R115  -  [R_S_1608]  231.75 121 270 bottom
R120  -  [R_S_1608]  176.25 40 180 bottom
R122  -  [R_S_1608]  176.25 41.5 180 bottom
R123  -  [R_S_1608]  176.25 43.5 180 bottom
R124  -  [R_S_1608]  198.75 45 180 bottom
R125  -  [R_S_1608]  202 45 180 bottom
R126  -  [R_S_1608]  205.25 45 180 bottom
R127  -  [R_S_1608]  208.5 45 180 bottom
R128  -  [R_S_1608]  211.75 45 180 bottom
R129  -  [R_S_1608]  176.25 45 180 bottom
R130  -  [R_S_1608]  193 39.25 270 bottom
R131  -  [R_S_1608]  196.25 42.5 270 bottom
R132  -  [R_S_2012]  192.5 52 180 bottom
R133  -  [R_S_1608]  150 32 270 top
R134  -  [R_S_1608]  154.5 145.5 270 bottom
R135  -  [R_S_1608]  156 145.5 270 bottom
R136  -  [R_S_1608]  157.5 145.5 270 bottom
R137  -  [R_S_1608]  159 145.5 270 bottom
R138  -  [R_S_1608]  153.75 188 270 bottom
R139  -  [R_S_1608]  155.25 188 270 bottom
R140  -  [R_S_1608]  156.75 188 270 bottom
R141  -  [R_S_1608]  158.25 188 270 bottom
R142  -  [R_S_1608]  159.75 188 270 bottom
R143  -  [R_S_1608]  164.75 188 270 bottom
R144  -  [R_S_1608]  159 174 270 bottom
R145  -  [R_S_1608]  161 174 270 bottom
R153  -  [R_S_1608]  153.75 77.5 180 top
R154  -  [R_S_1608]  153.75 70 180 top
R155  -  [R_S_1608]  153.75 79 0 top
R156  -  [R_S_1608]  153.75 68.5 0 top
R157  -  [R_S_1608]  168.75 77.5 180 top
R158  -  [R_S_1608]  168.75 79 0 top
R159  -  [R_S_1608]  168.75 70 180 top
R160  -  [R_S_1608]  168.75 68.5 0 top
R161  -  [R_S_1608]  219.05 257.75 90 top
R162  -  [R_S_1608]  215.5 258.25 0 top
R163  -  [R_S_1608]  215.5 256.5 0 top
R164  -  [R_S_1608]  219.05 219.75 90 top
R165  -  [R_S_1608]  215.5 220.25 0 top
R166  -  [R_S_1608]  215.5 218.5 0 top
R167  -  [R_S_1608]  219.05 169.75 90 top
R168  -  [R_S_1608]  215.5 170.25 0 top
R169  -  [R_S_1608]  215.5 168.5 0 top
R170  -  [R_S_1608]  219.05 131.75 90 top
R171  -  [R_S_1608]  215.5 132.25 0 top
R172  -  [R_S_1608]  215.5 130.5 0 top
R173  -  [R_S_2012]  106 112 0 bottom
R174  -  [R_S_2012]  106 150 0 bottom
R175  -  [R_S_2012]  106 200 0 bottom
R176  -  [R_S_2012]  106 238 0 bottom
R177  -  [R_S_2012]  214 253 180 bottom
R178  -  [R_S_2012]  214 215 180 bottom
R179  -  [R_S_2012]  214 165 180 bottom
R180  -  [R_S_2012]  214 127 180 bottom
TB1  -  [TB_D_OP_057]  48 7.5 180 top
TB2  -  [TB_D_OP_057]  85 7.5 180 top
TB3  -  [TB_D_OP_057]  25 272.5 180 top
TB4  -  [TB_D_OP_057]  55 272.5 0 top
TB5  -  [TB_D_OP_057]  265 272.5 0 top
TB6  -  [TB_D_OP_057]  295 272.5 180 top
TB7  -  [TB_D_OP_057]  269 7.5 0 top
TB8  -  [TB_D_OP_057]  238.5 7.5 0 top
TP1  -  [TP_HK_3_G]  147.5 38.75 180 top
TP2  -  [TP_HK_3_G]  103.5 118 90 top
TP3  -  [TP_HK_3_G]  113.5 116 90 top
TP4  -  [TP_HK_3_G]  87.25 107.5 90 top
TP5  -  [TP_HK_3_G]  87.25 119.5 90 top
TP6  -  [TP_HK_3_G]  98 119.5 90 top
TP7  -  [TP_HK_3_G]  103.5 156 90 top
TP8  -  [TP_HK_3_G]  113.5 154 90 top
TP9  -  [TP_HK_3_G]  87.25 145.5 90 top
TP10  -  [TP_HK_3_G]  87.25 157.5 90 top
TP11  -  [TP_HK_3_G]  98 157.5 90 top
TP12  -  [TP_HK_3_G]  103.5 206 90 top
TP13  -  [TP_HK_3_G]  113.5 204 90 top
TP14  -  [TP_HK_3_G]  87.25 195.5 90 top
TP15  -  [TP_HK_3_G]  87.25 207.5 90 top
TP16  -  [TP_HK_3_G]  98 207.5 90 top
TP17  -  [TP_HK_3_G]  103.5 244 90 top
TP18  -  [TP_HK_3_G]  113.5 242 90 top
TP19  -  [TP_HK_3_G]  87.25 233.5 90 top
TP20  -  [TP_HK_3_G]  87.25 245.5 90 top
TP21  -  [TP_HK_3_G]  98 245.5 90 top
TP22  -  [TP_HK_3_G]  216.5 247 270 top
TP23  -  [TP_HK_3_G]  206.5 249 270 top
TP24  -  [TP_HK_3_G]  232.75 257.5 270 top
TP25  -  [TP_HK_3_G]  232.75 245.5 270 top
TP26  -  [TP_HK_3_G]  222 245.5 270 top
TP27  -  [TP_HK_3_G]  216.5 209 270 top
TP28  -  [TP_HK_3_G]  206.5 211 270 top
TP29  -  [TP_HK_3_G]  232.75 219.5 270 top
TP30  -  [TP_HK_3_G]  232.75 207.5 270 top
TP31  -  [TP_HK_3_G]  222 207.5 270 top
TP32  -  [TP_HK_3_G]  216.5 159 270 top
TP33  -  [TP_HK_3_G]  206.5 161 270 top
TP34  -  [TP_HK_3_G]  232.75 169.5 270 top
TP35  -  [TP_HK_3_G]  232.75 157.5 270 top
TP36  -  [TP_HK_3_G]  222 157.5 270 top
TP37  -  [TP_HK_3_G]  216.5 121 270 top
TP38  -  [TP_HK_3_G]  206.5 123 270 top
TP39  -  [TP_HK_3_G]  232.75 131.5 270 top
TP40  -  [TP_HK_3_G]  232.75 119.5 270 top
TP41  -  [TP_HK_3_G]  222 119.5 270 top
TP42  -  [TP_HK_3_G]  172.5 25 0 top
TP43  -  [TP_HK_3_G]  145 262 90 top
TP44  -  [TP_HK_3_G]  160 20 180 top
TP45  -  [TP_HK_3_G]  150 20 0 top
TP46  -  [TP_HK_3_G]  175 262 270 top
TP47  -  [TP_HK_3_G]  137.5 114.5 90 top
TP48  -  [TP_HK_3_G]  137.5 152.5 90 top
TP49  -  [TP_HK_3_G]  137.5 202.5 90 top
TP50  -  [TP_HK_3_G]  137.5 240.5 90 top
TP51  -  [TP_HK_3_G]  182.5 250.5 270 top
TP52  -  [TP_HK_3_G]  182.5 212.5 90 top
TP53  -  [TP_HK_3_G]  182.5 162.5 90 top
TP54  -  [TP_HK_3_G]  182.5 124.5 90 top
TP55  -  [TP_HK_3_G]  137.5 248.5 270 top
TP56  -  [TP_HK_3_G]  182.5 116.5 90 top
TP57  -  [TP_HK_3_G]  147.5 43.75 0 top
TP58  -  [TP_HK_3_G]  172.5 20 0 top
TP59  -  [TP_HK_3_G]  161.25 72.5 180 top

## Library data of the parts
C1 C10 C11 C13 C16 C17 C25 C45 C57 C77 C87 C107 C119 C139 C146 C153 C155 C158 C160 C161 C164 C165 C172 C174 C175 = C-GRM188R71A105KA61D
C2-C7 C147-C152 = C-ESMR451VSN471MR40S
C8 = C-GRM1555C1H102JA01D
C12 C15 C154 C159 C168 C170 C171 C173 = C-GRM1885C1H471JA01D
C14 C157 = C-GRM1885C1H331JA01D
C18 C20 C23 C24 C38 C40 C43 C44 C50 C52 C55 C56 C70 C72 C75 C76 C84 C86 C88 C89 C104 C106 C108 C109 C116 C118 C120 C121 C136 C138 C140 C141 = C-GRM188R61H105KAALD
C19 C27 C39 C47 C51 C59 C71 C79 C85 C90 C105 C110 C117 C122 C137 C142 C166 C167 = C-1608_NM
C21 C22 C41 C42 C53 C54 C73 C74 C82 C83 C102 C103 C114 C115 C134 C135 = C-GRM31CR61H106MA12L
C26 C46 C58 C78 = C-GRM1885C1H332JA01D
C28 C29 C32-C37 C62-C69 = C-CKG57NX7T2J105M500JH
C31 C49 C61 C81 C92 C112 C124 C144 = C-GRM21BC71E106KE11L
C91 C111 C123 C143 = C-GRM1885C1H682JA01D
C94-C101 C126-C133 = C-CKG57NX7T2W225M500JH
C162 C163 = C-GRM31CR61H106KA12L
CN1 = CN-BM02B-PASS-TFT_LF_SN
CN2 = CN-BM03B-PASS-TFT_LF_SN
CN3 = CN-BM04B-PASS-TFT_LF_SN
CN4 = CN-WR-60S-VFH05-N1
CT1 = CT-F02P025S05L
CT2 = CT-F02P050S05L
D2 D3 D10 D16 D22 D28 D35 D41 D47 D53 = D-CUS05F30
D5 D6 D56 D58 = D-DSR01S30SL
D7 D8 D13 D14 D19 D20 D25 D26 D31 D37 D43 D49 = D-CMF05
D9 D15 D21 D27 D33 D39 D45 D51 = D-CMS03
D11 D17 D23 D29 D34 D40 D46 D52 = D-CRY82
D12 D18 D24 D30 D36 D42 D48 D54 = D-KDZVTR2.0B
D59-D66 = D-TO-247_NM
IC1 IC24 = IC-OPA4322AIPWR
IC2 IC20 = IC-TLP7920_LF5_TP5
IC3 IC5 IC7 IC9 = IC-LP2951D
IC4 IC6 IC8 IC10 IC12 IC14 IC16 IC18 = IC-TLP5214A
IC11 IC13 IC15 IC17 = IC-LP2951D_NM
IC19 = IC-OPA2322AID
IC21 IC22 = IC-TC74VHC541FT
IC23 = IC-REF2025AIDDCT
L1 = L-MBKK1608T1R0M
LED1 = LED-VCDG1111C-4BY3C-TR
PS1 PS10 = PS-R05P05S
PS2-PS9 = PS-G2412S-2WR2
PS11 = PS-MGFS102405
Q1-Q4 = Q-TW070J120B_REVERSE
Q5-Q8 = Q-TK49N65W5_REVERSE
R1 R2 R4 R7 = R-ROX5SJ100K
R3 R155 R156 R158 R160 = R-RK73H1JTTD2002F
R5 R28 R40 R52 R64 R75 R87 R99 R111 = R-RK73H1JTTD1001F
R8 R18 R120 R129 = R-RK73G1JTTD3602F
R9 R16 R122 R123 = R-RK73G1JTTD1202F
R10-R14 = R-RK73H2ATTD3303F
R15 = R-RK73G1JTTD3600F
R17 R130 R161 R163 R164 R166 R167 R169 R170 R172 = R-RK73Z1JTTD
R19 R132 = R-RK73B2ATTD471J
R20 R34 R44 R56 R69 R81 R93 R105 = R-RK73H1JTTD7502F
R21 R32 R45 R57 R68 R80 R92 R104 = R-RK73H1JTTD8202F
R22 R33 R46 R58 R70 R82 R94 R106 R134-R141 R153 R154 R157 R159 = R-RK73H1JTTD1002F
R23 R35 R47 R59 R71 R83 R95 R107 R133 = R-RK73B1JTTD471J
R24 R36 R48 R60 = R-ERJ3EKF4700V
R25 R37 R49 R61 R73 R85 R97 R109 R162 R165 R168 R171 = R-1608_NM
R26 R38 R50 R62 = R-ERJ1TYJ3R3U
R27 R39 R51 R63 = R-ERJ1TYJ4R7U
R29 R41 R53 R65 R79 R91 R103 R115 = R-RK73B1JTTD103J
R30 R31 R42 R43 R54 R55 R66 R67 R77 R78 R89 R90 R101 R102 R113 R114 = R-RK73H1JTTD6801F
R72 R84 R96 R108 = R-ERJ3EKF9101V
R74 R86 R98 R110 = R-ERJ1TYJ100U
R76 R88 R100 R112 = R-ERJ1TYJ470U
R124-R128 = R-ERJ3EKF1803V
R131 = R-RK73G1JTTD3900F
R142 R143 = R-RK73B1JTTD472J
R144 R145 = R-ERJ3EKF1000V
R173-R180 = R-RK73Z2ATTD
TB1-TB8 = TB-OP-057
TP1-TP59 = TP-HK-3-G

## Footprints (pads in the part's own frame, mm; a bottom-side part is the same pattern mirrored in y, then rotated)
C_D_ESMR_VS_30_0X40__1
  round 3 hole 2: 1(-3.535,-3.535) 2(3.535,3.535)
C_S_1005
  custom 0.113x0.113 smd: 1(-0.475,0) 2(0.475,0)
C_S_1608
  custom 0.2x0.2 smd: 1(-0.8,0) 2(0.8,0)
C_S_2012
  custom 0.2x0.2 smd: 1(-0.9,0) 2(0.9,0)
C_S_3216_T1_8
  custom 0.3x0.3 smd: 1(-1.4,0) 2(1.4,0)
C_S_CKG57_6050
  rect 2x5 smd: 1(-3,0) 2(3,0)
CN_S_BM02B_PASS_TFT__1
  rect 1x2.9 smd: 1(1,3.3) 2(-1,3.3)
  rect 1.8x3.6 smd: NC1(3.35,-1.35) NC2(-3.35,-1.35)
CN_S_BM03B_PASS_TFT__1
  rect 1x2.9 smd: 1(2,3.3) 2(0,3.3) 3(-2,3.3)
  rect 1.8x3.6 smd: NC1(4.35,-1.35) NC2(-4.35,-1.35)
CN_S_BM04B_PASS_TFT__1
  rect 1x2.9 smd: 1(3,3.3) 2(1,3.3) 3(-1,3.3) 4(-3,3.3)
  rect 1.8x3.6 smd: NC1(5.35,-1.35) NC2(-5.35,-1.35)
CN_S_WR_60S_VFH05_N1
  custom 0.156x0.156 smd: 1(-7.438,-2.1) 2(-7.438,2.1) 59(7.438,-2.1) 60(7.438,2.1)
  rect 0.25x1.8 smd: 3(-6.75,-2.1) 4(-6.75,2.1) 5(-6.25,-2.1) 6(-6.25,2.1) 7(-5.75,-2.1) 8(-5.75,2.1) 9(-5.25,-2.1) 10(-5.25,2.1) 11(-4.75,-2.1) 12(-4.75,2.1) 13(-4.25,-2.1) 14(-4.25,2.1) 15(-3.75,-2.1) 16(-3.75,2.1) 17(-3.25,-2.1) 18(-3.25,2.1) 19(-2.75,-2.1) 20(-2.75,2.1) 21(-2.25,-2.1) 22(-2.25,2.1) 23(-1.75,-2.1) 24(-1.75,2.1) 25(-1.25,-2.1) 26(-1.25,2.1) 27(-0.75,-2.1) 28(-0.75,2.1) 29(-0.25,-2.1) 30(-0.25,2.1) 31(0.25,-2.1) 32(0.25,2.1) 33(0.75,-2.1) 34(0.75,2.1) 35(1.25,-2.1) 36(1.25,2.1) 37(1.75,-2.1) 38(1.75,2.1) 39(2.25,-2.1) 40(2.25,2.1) 41(2.75,-2.1) 42(2.75,2.1) 43(3.25,-2.1) 44(3.25,2.1) 45(3.75,-2.1) 46(3.75,2.1) 47(4.25,-2.1) 48(4.25,2.1) 49(4.75,-2.1) 50(4.75,2.1) 51(5.25,-2.1) 52(5.25,2.1) 53(5.75,-2.1) 54(5.75,2.1) 55(6.25,-2.1) 56(6.25,2.1) 57(6.75,-2.1) 58(6.75,2.1)
CT_D_F02PXXXS05L
  round 2 hole 1.2: 1(-1.75,6.35) 2(0.79,6.35) 3(3.33,6.35) 8(3.33,-6.35) 9(0.79,-6.35) 10(-1.75,-6.35)
  oval 2x1.5 hole 0.9: 11(-9.37,-2.857) 12(-9.37,-0.953) 13(-9.37,0.953) 14(-9.37,2.857)
D_D_TO_247_3_AK_REVE_1
  round 0.01 hole 2x4 unplated: (-2.725,-1.3) (2.725,-1.3)
  round 0.01 hole 6.4 unplated: (0,20)
  round 2.5 hole 1.5: A1(5.45,-2.6) A3(-5.45,-2.6) K2(0,0)
D_S_1_1E1A_USC_AK
  rect 0.8x0.9 smd: A(-1.15,0) K(1.15,0)
D_S_FLAT_3_2A1S
  rect 1.2x1.2 smd: A(-1.4,0) K(1.4,0)
D_S_M_FLAT_3_4E1A_AK
  custom 0.35x0.35 smd: A(-2.2,0) K(2.2,0)
D_S_SOD_123_PMDU_AK
  rect 1x1.2 smd: A(-1.6,0) K(1.6,0)
D_S_SOD_962_SL2_AK
  rect 0.21x0.32 smd: A(0.205,0) K(-0.205,0)
IC_D_MGFS10_COSEL
  round 1.6 hole 0.8: 1(-8.89,0) 2(-6.35,0) 3(-3.81,0) 5(1.27,0) 6(3.81,0) 7(6.35,0) 8(8.89,0)
IC_D_RXXPXX
  round 1.6 hole 0.8: 1(-7.62,0) 2(-5.08,0) 5(2.54,0) 6(5.08,0) 7(7.62,0)
IC_SOP5_0_95_DDC
  custom 0.125x0.125 smd: 1(1.2,-0.95) 2(1.2,0) 3(1.2,0.95) 4(-1.2,0.95) 5(-1.2,-0.95)
IC_SOP8_1_27_D
  custom 0.163x0.163 smd: 1(-1.905,-2.435) 2(-0.635,-2.435) 3(0.635,-2.435) 4(1.905,-2.435) 5(1.905,2.435) 6(0.635,2.435) 7(-0.635,2.435) 8(-1.905,2.435)
IC_SOP8_2_54_11_10C4_1
  rect 1.5x1.6 smd: 1(-3.81,-4.35) 2(-1.27,-4.35) 3(1.27,-4.35) 4(3.81,-4.35) 5(3.81,4.35) 6(1.27,4.35) 7(-1.27,4.35) 8(-3.81,4.35)
IC_SOP14_0_65_PW
  custom 0.131x0.131 smd: 1(-2.038,-2.9) 7(2.038,-2.9) 8(2.038,2.9) 14(-2.038,2.9)
  custom 0.087x0.087 smd: 2(-1.3,-2.9) 3(-0.65,-2.9) 4(0,-2.9) 5(0.65,-2.9) 6(1.3,-2.9) 9(1.3,2.9) 10(0.65,2.9) 11(0,2.9) 12(-0.65,2.9) 13(-1.3,2.9)
IC_SOP16_1_27_11_10M_1
  custom 0.163x0.163 smd: 1(-4.445,-4.58) 2(-3.175,-4.58) 3(-1.905,-4.58) 4(-0.635,-4.58) 5(0.635,-4.58) 6(1.905,-4.58) 7(3.175,-4.58) 8(4.445,-4.58) 9(4.445,4.58) 10(3.175,4.58) 11(1.905,4.58) 12(0.635,4.58) 13(-0.635,4.58) 14(-1.905,4.58) 15(-3.175,4.58) 16(-4.445,4.58)
IC_SOP20_0_65_FT
  custom 0.131x0.131 smd: 1(-3.013,-2.9) 10(3.013,-2.9) 11(3.013,2.9) 20(-3.013,2.9)
  custom 0.087x0.087 smd: 2(-2.275,-2.9) 3(-1.625,-2.9) 4(-0.975,-2.9) 5(-0.325,-2.9) 6(0.325,-2.9) 7(0.975,-2.9) 8(1.625,-2.9) 9(2.275,-2.9) 12(2.275,2.9) 13(1.625,2.9) 14(0.975,2.9) 15(0.325,2.9) 16(-0.325,2.9) 17(-0.975,2.9) 18(-1.625,2.9) 19(-2.275,2.9)
L_S_MBKK1608
  rect 0.55x1 smd: 1(-0.625,0) 2(0.625,0)
LED_S_1608_AK
  custom 0.2x0.2 smd: A(-0.8,0) K(0.8,0)
PS_D_S_2WR2_MORNSUN
  round 1.8 hole 1: 1(-7.62,0) 2(-5.08,0) 5(2.54,0) 6(5.08,0) 7(7.62,0)
Q_D_TO_247_3_GDS_SP__1
  round 0.01 hole 2x4 unplated: (-2.725,-1.3) (2.725,-1.3)
  round 0.01 hole 6.4 unplated: (0,20)
  round 2.5 hole 1.5: D(0,0) G(5.45,-2.6) S(-5.45,-2.6)
R_D_ROX5S
  round 1.7 hole 0.95: 1(-15,0) 2(15,0)
R_S_1608
  custom 0.2x0.2 smd: 1(-0.8,0) 2(0.8,0)
R_S_2012
  custom 0.2x0.2 smd: 1(-0.9,0) 2(0.9,0)
R_S_6432
  custom 0.487x0.487 smd: 1(-2.725,0) 2(2.725,0)
TB_D_OP_057
  oval 4x6 hole 2x4: 1(-5.4,-3.5) 2(-5.4,3.5) 3(5.4,3.5) 4(5.4,-3.5)
TP_HK_3_G
  custom 0.425x0.425 smd: 1(0,0)
unnamed
  round 0.01 hole 3.5 unplated: (0,0)
unnamed#3
  round 0.01 hole 3.5 unplated: (-38,-1) (78,-1)

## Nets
+5V: C1.1(TP-1) C10.1(TP-1) C13.1(TP-1) C17.1(TP-1) C25.1(TP-1) C45.1(TP-1) C57.1(TP-1) C77.1(TP-1) C87.1(TP-1) C107.1(TP-1) C119.1(TP-1) C139.1(TP-1) C146.1(TP-1) C153.1(TP-1) C158.1(TP-1) C160.1(TP-1) C163.1(TP-1) C164.1(TP-1) C165.1(TP-1) C172.1(TP-1) C174.1(TP-1) CN4.1 CN4.2 CN4.3 CN4.4 CT1.14 CT2.14 D2.K IC1.4 IC2.8 IC4.2 IC6.2 IC8.2 IC10.2 IC12.2 IC14.2 IC16.2 IC18.2 IC19.8 IC20.8 IC21.20 IC22.20 IC23.3 IC23.4 IC24.4 PS1.1 PS10.1 PS11.6 R3.1(TP-1) R23.1(TP-1) R35.1(TP-1) R47.1(TP-1) R59.1(TP-1) R71.1(TP-1) R83.1(TP-1) R95.1(TP-1) R107.1(TP-1) R133.1(TP-1) R134.1(TP-1) R135.1(TP-1) R136.1(TP-1) R137.1(TP-1) R138.1(TP-1) R139.1(TP-1) R140.1(TP-1) R141.1(TP-1) R142.1(TP-1) R143.1(TP-1) TP44.1
+5V_DC_PRI: C11.1(TP-1) C16.1(TP-1) D5.K IC2.1 PS1.7 R19.1(TP-1)
+5V_DC_SEC: C155.1(TP-1) C161.1(TP-1) D56.K IC20.1 PS10.7 R132.1(TP-1)
+12V_Q5: C85.1(TP-1) C86.1(TP-1) C88.1(TP-1) C89.1(TP-1) IC11.1 IC12.13 R68.1(TP-1) R77.1(TP-1) R78.1(TP-1) R161.2 TP22.1
+12V_Q6: C105.1(TP-1) C106.1(TP-1) C108.1(TP-1) C109.1(TP-1) IC13.1 IC14.13 R80.1(TP-1) R89.1(TP-1) R90.1(TP-1) R164.2 TP27.1
+12V_Q7: C117.1(TP-1) C118.1(TP-1) C120.1(TP-1) C121.1(TP-1) IC15.1 IC16.13 R92.1(TP-1) R101.1(TP-1) R102.1(TP-1) R167.2 TP32.1
+12V_Q8: C137.1(TP-1) C138.1(TP-1) C140.1(TP-1) C141.1(TP-1) IC17.1 IC18.13 R104.1(TP-1) R113.1(TP-1) R114.1(TP-1) R170.2 TP37.1
+20V_Q1: C18.1(TP-1) C19.1(TP-1) C23.1(TP-1) C24.1(TP-1) IC3.1 IC4.13 R21.1(TP-1) R30.1(TP-1) R31.1(TP-1) TP2.1
+20V_Q2: C38.1(TP-1) C39.1(TP-1) C43.1(TP-1) C44.1(TP-1) IC5.1 IC6.13 R32.1(TP-1) R42.1(TP-1) R43.1(TP-1) TP7.1
+20V_Q3: C50.1(TP-1) C51.1(TP-1) C55.1(TP-1) C56.1(TP-1) IC7.1 IC8.13 R45.1(TP-1) R54.1(TP-1) R55.1(TP-1) TP12.1
+20V_Q4: C70.1(TP-1) C71.1(TP-1) C75.1(TP-1) C76.1(TP-1) IC9.1 IC10.13 R57.1(TP-1) R66.1(TP-1) R67.1(TP-1) TP17.1
+24V: C22.1(TP-1) C42.1(TP-1) C54.1(TP-1) C74.1(TP-1) C82.1(TP-1) C102.1(TP-1) C114.1(TP-1) C134.1(TP-1) C162.1(TP-1) CN2.1 CN3.1 CN3.3 L1.1(TP-1) PS2.1 PS3.1 PS4.1 PS5.1 PS6.1 PS7.1 PS8.1 PS9.1 TP43.1
GND: C1.2 C8.2 C10.2 C12.1(TP-1) C13.2 C17.2 C25.2 C45.2 C57.2 C77.2 C87.2 C107.2 C119.2 C139.2 C146.2 C153.2 C158.2 C159.1(TP-1) C160.2 C163.2 C164.2 C165.2 C166.2 C167.2 C172.2 C174.2 C175.2 CN1.2 CN4.5 CN4.6 CN4.7 CN4.8 CN4.11 CN4.12 CN4.15 CN4.16 CN4.19 CN4.20 CN4.23 CN4.24 CN4.31 CN4.32 CN4.39 CN4.40 CN4.50 CN4.59 CN4.60 CT1.13 CT2.13 D3.A IC1.11 IC2.5 IC4.1 IC4.4 IC6.1 IC6.4 IC8.1 IC8.4 IC10.1 IC10.4 IC12.1 IC12.4 IC14.1 IC14.4 IC16.1 IC16.4 IC18.1 IC18.4 IC19.4 IC20.5 IC21.1 IC21.6 IC21.7 IC21.8 IC21.9 IC21.10 IC21.19 IC22.1 IC22.8 IC22.9 IC22.10 IC22.19 IC23.2 IC24.11 LED1.K PS1.2 PS10.2 PS11.7 R8.1(TP-1) R129.1(TP-1) TP45.1
GND_24V: C22.2 C42.2 C54.2 C74.2 C82.2 C102.2 C114.2 C134.2 C162.2 CN2.3 CN3.2 CN3.4 PS2.2 PS3.2 PS4.2 PS5.2 PS6.2 PS7.2 PS8.2 PS9.2 PS11.1 TP46.1
GND_DC_PRI: C11.2 C16.2 IC2.4 PS1.5 R17.2 R19.2
GND_DC_SEC: C155.2 C161.2 IC20.4 PS10.5 R130.2 R132.2
GND_Q1: C18.2 C20.2 C21.2 C24.2 C31.2 D12.A IC3.3 IC3.4 IC4.9 IC4.12 PS2.5 R22.2 R173.2 TP6.1
GND_Q2: C38.2 C40.2 C41.2 C44.2 C49.2 D18.A IC5.3 IC5.4 IC6.9 IC6.12 PS3.5 R33.2 R174.2 TP11.1
GND_Q3: C50.2 C52.2 C53.2 C56.2 C61.2 D24.A IC7.3 IC7.4 IC8.9 IC8.12 PS4.5 R46.2 R175.2 TP16.1
GND_Q4: C70.2 C72.2 C73.2 C76.2 C81.2 D30.A IC9.3 IC9.4 IC10.9 IC10.12 PS5.5 R58.2 R176.2 TP21.1
GND_Q5: C83.2 C84.2 C86.2 C88.2 C92.2 D36.A IC11.3 IC11.4 IC12.9 IC12.12 PS6.5 R70.2 R177.2 TP26.1
GND_Q6: C103.2 C104.2 C106.2 C108.2 C112.2 D42.A IC13.3 IC13.4 IC14.9 IC14.12 PS7.5 R82.2 R178.2 TP31.1
GND_Q7: C115.2 C116.2 C118.2 C120.2 C124.2 D48.A IC15.3 IC15.4 IC16.9 IC16.12 PS8.5 R94.2 R179.2 TP36.1
GND_Q8: C135.2 C136.2 C138.2 C140.2 C144.2 D54.A IC17.3 IC17.4 IC18.9 IC18.12 PS9.5 R106.2 R180.2 TP41.1
/DI0_BI: CN4.51 R144.2
/DI1_BI: CN4.52 R145.2
/FLT_OUT_HV: C167.1(TP-1) IC4.3 IC6.3 IC8.3 IC10.3 IC22.6 R142.2 TP55.1
/FLT_OUT_LV: C166.1(TP-1) IC12.3 IC14.3 IC16.3 IC18.3 IC22.7 R143.2 TP56.1
/PWM2A_BO: CN4.27 IC21.2 R134.2
/PWM2B_BO: CN4.28 IC21.3 R135.2
/PWM3A_BO: CN4.29 IC21.4 R136.2
/PWM3B_BO: CN4.30 IC21.5 R137.2
/PWM5A_BO: CN4.35 IC22.2 R138.2
/PWM5B_BO: CN4.36 IC22.3 R139.2
/PWM6A_BO: CN4.37 IC22.4 R140.2
/PWM6B_BO: CN4.38 IC22.5 R141.2
/PWM_2A: IC4.5 IC4.8 IC21.18 R28.2 TP47.1
/PWM_2B: IC6.5 IC6.8 IC21.17 R40.2 TP48.1
/PWM_3A: IC8.5 IC8.8 IC21.16 R52.2 TP49.1
/PWM_3B: IC10.5 IC10.8 IC21.15 R64.2 TP50.1
/PWM_5A: IC12.5 IC12.8 IC22.18 R75.2 TP51.1
/PWM_5B: IC14.5 IC14.8 IC22.17 R87.2 TP52.1
/PWM_6A: IC16.5 IC16.8 IC22.16 R99.2 TP53.1
/PWM_6B: IC18.5 IC18.8 IC22.15 R111.2 TP54.1
AD0: C15.1(TP-1) CN4.9 IC19.1 R18.1(TP-1)
AD1: CN4.10 IC19.6 IC19.7
AD2: C168.2 CN4.13 IC1.14 R155.1(TP-1)
AD3: C154.1(TP-1) CN4.14 IC24.8 R120.1(TP-1)
AD4: C171.2 CN4.17 IC24.14 R158.1(TP-1)
HV_DC_CURRENT: CT1.12 IC1.5 TP1.1
HV_DC_CURRENT_REF: CT1.11 IC1.3 TP57.1
HV_DC_N: C5.2 C6.2 C7.2 C14.2 C34.2 C35.2 C36.2 C37.2 C43.2 C46.2 C47.2 C49.1(TP-1) C66.2 C67.2 C68.2 C69.2 C75.2 C78.2 C79.2 C81.1(TP-1) D6.A D16.A D17.A D18.K D28.A D29.A D30.K D60.A1 D60.A3 D62.A1 D62.A3 IC2.3 IC6.16 IC10.16 Q2.S Q4.S R7.2 R15.2 R17.1(TP-1) R41.2 R42.2 R43.2 R65.2 R66.2 R67.2 R174.1(TP-1) R176.1(TP-1) TB2.1 TB2.2 TB2.3 TB2.4 TP10.1 TP20.1
HV_DC_P: C2.1(TP-1) C3.1(TP-1) C4.1(TP-1) C28.1(TP-1) C29.1(TP-1) C32.1(TP-1) C33.1(TP-1) C62.1(TP-1) C63.1(TP-1) C64.1(TP-1) C65.1(TP-1) CT1.8 CT1.9 CT1.10 D7.K D19.K D59.K2 D61.K2 Q1.D Q3.D R1.1(TP-1) R10.1(TP-1)
LV_DC_CURRENT: CT2.12 IC24.5 TP42.1
LV_DC_CURRENT_REF: CT2.11 IC24.3 TP58.1
LV_DC_N: C98.2 C99.2 C100.2 C101.2 C109.2 C110.2 C111.2 C112.1(TP-1) C130.2 C131.2 C132.2 C133.2 C141.2 C142.2 C143.2 C144.1(TP-1) C147.2 C148.2 C149.2 C150.2 C151.2 C152.2 C157.2 D40.A D41.A D42.K D52.A D53.A D54.K D58.A D64.A1 D64.A3 D66.A1 D66.A3 IC14.16 IC18.16 IC20.3 Q6.S Q8.S R89.2 R90.2 R91.2 R113.2 R114.2 R115.2 R130.1(TP-1) R131.2 R178.1(TP-1) R180.1(TP-1) TB8.1 TB8.2 TB8.3 TB8.4 TP30.1 TP40.1
LV_DC_P: C94.1(TP-1) C95.1(TP-1) C96.1(TP-1) C97.1(TP-1) C126.1(TP-1) C127.1(TP-1) C128.1(TP-1) C129.1(TP-1) C147.1(TP-1) C148.1(TP-1) C149.1(TP-1) C150.1(TP-1) C151.1(TP-1) C152.1(TP-1) CT2.1 CT2.2 CT2.3 D31.K D43.K D63.K2 D65.K2 Q5.D Q7.D R128.1(TP-1)
N15594553: C26.1(TP-1) D9.A IC4.10 Q1.G R27.2 R29.1(TP-1) TP4.1
N15594563: C23.2 C26.2 C27.2 C31.1(TP-1) D10.A D11.A D12.K D13.K D59.A1 D59.A3 D60.K2 IC4.16 Q1.S Q2.D R29.2 R30.2 R31.2 R173.1(TP-1) TB3.1 TB3.2 TB3.3 TB3.4 TP5.1
N15594591: C27.1(TP-1) D10.K D11.K IC4.14 R24.1(TP-1) R25.1(TP-1) TP3.1
N15594597: IC4.11 R25.2 R26.2 R27.1(TP-1)
N15594617: D8.A R24.2
N15594699: IC4.6 IC4.7 R23.2 R28.1(TP-1)
N15594743: C20.1(TP-1) C21.1(TP-1) IC3.8 PS2.7
N15594761: C19.2 IC3.7 R20.2 R22.1(TP-1)
N15594765: R20.1(TP-1) R21.2
N15594841: C40.1(TP-1) C41.1(TP-1) IC5.8 PS3.7
N15594863: C39.2 IC5.7 R33.1(TP-1) R34.2
N15594957: C47.1(TP-1) D16.K D17.K IC6.14 R36.1(TP-1) R37.1(TP-1) TP8.1
N15594961: D14.A R36.2
N15594967: IC6.6 IC6.7 R35.2 R40.1(TP-1)
N15595025: IC6.11 R37.2 R38.2 R39.1(TP-1)
N15595027: C46.1(TP-1) D15.A IC6.10 Q2.G R39.2 R41.1(TP-1) TP9.1
N15595143: C28.2 C29.2 C32.2 C33.2 C34.1(TP-1) C35.1(TP-1) C36.1(TP-1) C37.1(TP-1)
N15597681: C58.1(TP-1) D21.A IC8.10 Q3.G R51.2 R53.1(TP-1) TP14.1
N15597691: C55.2 C58.2 C59.2 C61.1(TP-1) D22.A D23.A D24.K D25.K D61.A1 D61.A3 D62.K2 IC8.16 Q3.S Q4.D R53.2 R54.2 R55.2 R175.1(TP-1) TB4.1 TB4.2 TB4.3 TB4.4 TP15.1
N15597719: C59.1(TP-1) D22.K D23.K IC8.14 R48.1(TP-1) R49.1(TP-1) TP13.1
N15597725: IC8.11 R49.2 R50.2 R51.1(TP-1)
N15597745: D20.A R48.2
N15597827: IC8.6 IC8.7 R47.2 R52.1(TP-1)
N15597871: C52.1(TP-1) C53.1(TP-1) IC7.8 PS4.7
N15597889: C51.2 IC7.7 R44.2 R46.1(TP-1)
N15597969: C72.1(TP-1) C73.1(TP-1) IC9.8 PS5.7
N15597991: C71.2 IC9.7 R56.2 R58.1(TP-1)
N15598085: C79.1(TP-1) D28.K D29.K IC10.14 R60.1(TP-1) R61.1(TP-1) TP18.1
N15598089: D26.A R60.2
N15598095: IC10.6 IC10.7 R59.2 R64.1(TP-1)
N15598153: IC10.11 R61.2 R62.2 R63.1(TP-1)
N15598155: C78.1(TP-1) D27.A IC10.10 Q4.G R63.2 R65.1(TP-1) TP19.1
N15598271: C62.2 C63.2 C64.2 C65.2 C66.1(TP-1) C67.1(TP-1) C68.1(TP-1) C69.1(TP-1)
N15653119: D21.K R50.1(TP-1)
N15653689: D27.K R62.1(TP-1)
N15654705: D9.K R26.1(TP-1)
N16689323: C8.1(TP-1) D2.A D3.K IC19.5 R5.1(TP-1)
N16721309: R32.2 R34.1(TP-1)
N16721684: R44.1(TP-1) R45.2
N16722059: R56.1(TP-1) R57.2
N16801736: D15.K R38.1(TP-1)
N17061964: D7.A D8.K
N17062012: D13.A D14.K
N17062059: D19.A D20.K
N17062107: D25.A D26.K
N17096645: CT1.1 CT1.2 CT1.3 TB1.1 TB1.2 TB1.3 TB1.4
N17096659: R1.2 R2.1(TP-1)
N17096693: C2.2 C3.2 C4.2 C5.1(TP-1) C6.1(TP-1) C7.1(TP-1) R2.2 R4.1(TP-1)
N17096757: R4.2 R7.1(TP-1)
N17096799: C12.2 IC19.3 R8.2 R9.2
N17096941: C15.2 IC19.2 R16.2 R18.2
N17096947: C14.1(TP-1) D5.A D6.K IC2.2 R14.2 R15.1(TP-1)
N17096957: R13.2 R14.1(TP-1)
N17096959: R12.2 R13.1(TP-1)
N17096961: R11.2 R12.1(TP-1)
N17096963: R10.2 R11.1(TP-1)
N17107990: L1.2 PS11.2
N17107994: LED1.A R133.2
N17108111: IC22.14 R144.1(TP-1)
N17108118: IC22.13 R145.1(TP-1)
N17110393: CT2.8 CT2.9 CT2.10 TB7.1 TB7.2 TB7.3 TB7.4
N17110606: C154.2 IC24.9 R120.2 R122.2
N17110732: IC20.6 R122.1(TP-1)
N17110830: C159.2 IC24.10 R123.2 R129.2
N17110836: IC20.7 R123.1(TP-1)
N17110838: C157.1(TP-1) D56.A D58.K IC20.2 R124.2 R131.1(TP-1)
N17110848: R124.1(TP-1) R125.2
N17110850: R125.1(TP-1) R126.2
N17110852: R126.1(TP-1) R127.2
N17110854: R127.1(TP-1) R128.2
N17112878: C83.1(TP-1) C84.1(TP-1) IC11.8 R161.1(TP-1) R162.2 R163.2
N17112898: C85.2 IC11.7 R69.2 R70.1(TP-1)
N17112910: R68.2 R69.1(TP-1)
N17113118: C89.2 C90.2 C91.2 C92.1(TP-1) D34.A D35.A D36.K D37.K D63.A1 D63.A3 D64.K2 IC12.16 Q5.S Q6.D R77.2 R78.2 R79.2 R177.1(TP-1) TB5.1 TB5.2 TB5.3 TB5.4 TP25.1
N17113144: IC12.6 IC12.7 R71.2 R75.1(TP-1)
N17113163: C90.1(TP-1) D34.K D35.K IC12.14 R72.2 R73.1(TP-1) TP23.1
N17113169: D31.A R72.1(TP-1)
N17113250: IC12.11 R73.2 R74.2 R76.2
N17113252: D33.K R74.1(TP-1)
N17113254: C91.1(TP-1) D33.A IC12.10 Q5.G R76.1(TP-1) R79.1(TP-1) TP24.1
N17113532: C94.2 C95.2 C96.2 C97.2 C98.1(TP-1) C99.1(TP-1) C100.1(TP-1) C101.1(TP-1)
N17113656: C103.1(TP-1) C104.1(TP-1) IC13.8 R164.1(TP-1) R165.2 R166.2
N17113676: C105.2 IC13.7 R81.2 R82.1(TP-1)
N17113688: R80.2 R81.1(TP-1)
N17113930: IC14.6 IC14.7 R83.2 R87.1(TP-1)
N17113949: C110.1(TP-1) D40.K D41.K IC14.14 R84.2 R85.1(TP-1) TP28.1
N17113955: D37.A R84.1(TP-1)
N17114036: IC14.11 R85.2 R86.2 R88.2
N17114038: D39.K R86.1(TP-1)
N17114040: C111.1(TP-1) D39.A IC14.10 Q6.G R88.1(TP-1) R91.1(TP-1) TP29.1
N17116276: C115.1(TP-1) C116.1(TP-1) IC15.8 R167.1(TP-1) R168.2 R169.2
N17116296: C117.2 IC15.7 R93.2 R94.1(TP-1)
N17116308: R92.2 R93.1(TP-1)
N17116516: C121.2 C122.2 C123.2 C124.1(TP-1) D46.A D47.A D48.K D49.K D65.A1 D65.A3 D66.K2 IC16.16 Q7.S Q8.D R101.2 R102.2 R103.2 R179.1(TP-1) TB6.1 TB6.2 TB6.3 TB6.4 TP35.1
N17116542: IC16.6 IC16.7 R95.2 R99.1(TP-1)
N17116561: C122.1(TP-1) D46.K D47.K IC16.14 R96.2 R97.1(TP-1) TP33.1
N17116567: D43.A R96.1(TP-1)
N17116648: IC16.11 R97.2 R98.2 R100.2
N17116650: D45.K R98.1(TP-1)
N17116652: C123.1(TP-1) D45.A IC16.10 Q7.G R100.1(TP-1) R103.1(TP-1) TP34.1
N17116930: C126.2 C127.2 C128.2 C129.2 C130.1(TP-1) C131.1(TP-1) C132.1(TP-1) C133.1(TP-1)
N17117054: C135.1(TP-1) C136.1(TP-1) IC17.8 R170.1(TP-1) R171.2 R172.2
N17117074: C137.2 IC17.7 R105.2 R106.1(TP-1)
N17117086: R104.2 R105.1(TP-1)
N17117328: IC18.6 IC18.7 R107.2 R111.1(TP-1)
N17117347: C142.1(TP-1) D52.K D53.K IC18.14 R108.2 R109.1(TP-1) TP38.1
N17117353: D49.A R108.1(TP-1)
N17117434: IC18.11 R109.2 R110.2 R112.2
N17117436: D51.K R110.1(TP-1)
N17117438: C143.1(TP-1) D51.A IC18.10 Q8.G R112.1(TP-1) R115.1(TP-1) TP39.1
N17146611: CN1.1 R3.2 R5.2
N17153025: IC2.7 R9.1(TP-1)
N17153280: IC2.6 R16.1(TP-1)
N17330270: C168.1(TP-1) IC1.13 R153.1(TP-1) R155.2
N17330302: IC1.1 IC1.2 R153.2
N17330344: IC1.6 IC1.7 R154.2
N17330348: C170.1(TP-1) IC1.12 R154.1(TP-1) R156.2
N17330358: C170.2 C173.2 IC1.8 IC1.9 R156.1(TP-1) R160.1(TP-1)
N17330496: C171.1(TP-1) IC24.13 R157.1(TP-1) R158.2
N17330528: IC24.1 IC24.2 R157.2
N17330570: IC24.6 IC24.7 R159.2
N17330574: C173.1(TP-1) IC24.12 R159.1(TP-1) R160.2
N17330740: C175.1(TP-1) IC1.10 IC23.5 TP59.1
N17391340: PS6.7 R162.1(TP-1)
N17392260: PS7.7 R165.1(TP-1)
N17392634: PS7.6 R166.1(TP-1)
N17392773: PS6.6 R163.1(TP-1)
N17393142: PS8.7 R168.1(TP-1)
N17393231: PS8.6 R169.1(TP-1)
N17393515: PS9.7 R171.1(TP-1)
N17393618: PS9.6 R172.1(TP-1)

Pads without a net: CN1 NC1 NC2; CN2 2 NC1 NC2; CN3 NC1 NC2; CN4 18 21 22 25 26 33 34 41 42 43 44 45 46 47 48 49 53 54 55 56 57 58; IC3 2 5 6; IC4 15; IC5 2 5 6; IC6 15; IC7 2 5 6; IC8 15; IC9 2 5 6; IC10 15; IC11 2 5 6; IC12 15; IC13 2 5 6; IC14 15; IC15 2 5 6; IC16 15; IC17 2 5 6; IC18 15; IC21 11 12 13 14; IC22 11 12; IC23 1; PS1 6; PS2 6; PS3 6; PS4 6; PS5 6; PS10 6; PS11 3 5 8

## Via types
v1: diameter 0.6, hole 0.3, TOP to BOTTOM, 421 vias
v2: diameter 1, hole 0.5, TOP to BOTTOM, 195 vias

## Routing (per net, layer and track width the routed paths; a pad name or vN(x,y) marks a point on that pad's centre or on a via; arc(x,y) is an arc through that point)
+5V: length 158.5
  TOP w0.2: 162.98,153.25 163.5,153.25 v1(164,152.75) ; 157.02,153.25 156.5,153.25 v1(156,152.75)
  TOP w0.25: CN4.3 162.98,153.25 ; CN4.4 157.02,153.25
  TOP w0.3: IC1.4 v1(149.5,73.75) ; 150.66,58.2 150.66,58.85 151,59.2 152.31,59.2 ; 160.3,80.2 160.3,81 160.45,81.15 160.45,82.06 ; v1(156,152.75) 156.31,152.56 157.31,152.56 ; 160.3,77.8 160.3,79.7 ; 177.83,27.8 176.7,27.8 v1(176.25,28.25) ; 178.19,27.8 179.3,27.8 179.36,27.86 180.88,27.86 ; v1(164,152.75) 163.69,152.56 162.86,152.56 ; 150,32.92 v1(150,34) ; 146.51,48 v1(144.75,48) ; 180,43.49 180,44.75 v1(178.75,46) ; v1(141.25,64.25) 140,65.5 140,66.76 ; v1(154,58.75) 153.55,59.2 152.54,59.2 ; 146.16,50 v1(144.75,50) ; IC24.4 v1(164.5,73.75) ; TP44.1 v1(158,20) ; 160.26,82.25 v1(159,82.25)
  TOP w0.5: 160.3,80.2 IC23.3 160.3,79.7 ; IC23.4 160.3,77.8 ; v1(143.75,35.75) 143.3,36.2 142.17,36.2 ; 141.72,36.2 140.7,36.2 140.64,36.14 139.12,36.14
  TOP w0.6: CN4.1 162.86,152.56 ; CN4.2 157.31,152.56 ; IC19.8 150.66,58.2
  TOP w0.8: 152.31,59.2 C158.1 152.54,59.2 ; 178.19,27.8 C146.1 177.83,27.8 ; C10.1 140,66.76 ; 160.45,82.06 C174.1 160.26,82.25 ; 142.17,36.2 C1.1 141.72,36.2 ; R133.1 150,32.92 ; 159.57,240.4 157.5,240.4 157.29,240.19 PS11.6 ; 160.16,240.4 161.91,240.4 v2(162.5,240.5) ; D2.K 146.16,50 ; R3.1 146.51,48 ; 180,43.49 C153.1
  TOP w1.2: 160.16,240.4 C163.1 159.57,240.4
  TOP w1.5: CT2.14 180.88,27.86 ; CT1.14 139.12,36.14
  CONDUCTIVE2 w0.3: 179.5,27.86 CT2.14 181.13,29.5 ; 138.87,34.5 CT1.14 140.5,36.14
  CONDUCTIVE2 w0.5: PS10.1 178.88,54.75 ; PS10.1 177.25,56.25 ; PS10.1 178.88,57.75 ; PS1.1 141.62,54.75 ; PS1.1 141.62,51.75 ; PS1.1 143.25,53.25
  BOTTOM w0.3: 156.94,188.8 158.06,188.8 ; 155.44,188.8 156.56,188.8 ; v1(178.75,46) 179.06,46.31 IC20.8 ; v1(155.25,134.25) 155.7,134.7 C164.1 ; 153.94,188.8 155.06,188.8 ; 154.5,146.42 v1(154.5,147.5) ; v1(125.8,201.1) 125.8,200.19 ; v1(125.8,113.1) 125.8,112.19 ; 152.76,73.75 v1(149.5,73.75) ; 167.76,73.75 v1(164.5,73.75) ; 158.49,178.2 158.49,179.21 158,179.7 156.69,179.7 ; v1(194.2,163.9) 194.2,164.81 ; 157.69,146.3 158.81,146.3 ; IC2.8 140.94,63.94 v1(141.25,64.25) ; v1(155.25,179.25) 155.7,179.7 C165.1 ; v1(194.2,251.9) 194.2,252.81 ; v1(125.8,151.1) 125.8,150.19 ; 158.49,133.2 158.49,133.96 157.75,134.7 156.69,134.7 ; 154.69,146.3 155.81,146.3 ; 156.19,146.3 157.31,146.3 ; v1(194.2,213.9) 194.2,214.81 ; v1(125.8,239.1) 125.8,238.19 ; 158.44,188.8 159.56,188.8 ; 164.75,188.92 164.75,190 163.5,191.25 v1(161.25,191.25) 160.75,191.25 159.75,190.25 159.75,188.99 ; v1(194.2,125.9) 194.2,126.81
  BOTTOM w0.5: 141.3,56.61 141.3,57.68 v1(141.62,58) ; PS10.1 178.88,54.07 C160.1 ; 124.03,117.2 123.55,117.17 122.48,117.17 ; 124.03,205.2 123.55,205.18 122.48,205.18 ; 141.3,56.23 141.3,54.95 141.62,54.63 PS1.1 ; 124.39,205.2 v1(125.3,205.2) ; v1(178.75,52) 179.2,52.45 179.2,53.58 ; 197.52,209.82 196.45,209.82 195.97,209.8 ; 124.39,243.2 v1(125.3,243.2) ; 124.03,155.2 123.55,155.18 122.48,155.18 ; 195.97,159.8 196.45,159.82 197.52,159.82 ; 195.97,247.8 196.45,247.82 197.52,247.82 ; 195.6,159.8 v1(194.7,159.8) ; 124.39,155.2 v1(125.3,155.2) ; 195.6,209.8 v1(194.7,209.8) ; 124.39,117.2 v1(125.3,117.2) ; 122.48,243.18 123.55,243.18 124.03,243.2 ; IC21.20 158.49,133.2 ; 195.97,121.8 196.45,121.83 197.52,121.83 ; IC22.20 158.49,178.2 ; 195.6,247.8 v1(194.7,247.8) ; 195.6,121.8 v1(194.7,121.8)
  BOTTOM w0.6: 122.48,205.18 IC8.2 ; 197.52,121.83 IC18.2 ; 122.48,243.18 IC10.2 ; 197.52,209.82 IC14.2 ; 122.48,117.17 IC4.2 ; 122.48,155.18 IC6.2 ; 197.52,247.82 IC12.2 ; 197.52,159.82 IC16.2
  BOTTOM w0.8: 124.03,117.2 C25.1 124.39,117.2 ; 194.2,164.81 R95.1 ; 124.39,155.2 C45.1 124.03,155.2 ; 124.03,205.2 C57.1 124.39,205.2 ; 141.3,56.61 C17.1 141.3,56.23 ; C172.1 167.76,73.75 ; 155.44,188.8 R139.1 155.06,188.8 ; 195.6,247.8 C87.1 195.97,247.8 ; 159.56,188.8 R142.1 159.75,188.99 ; R143.1 164.75,188.92 ; 194.2,126.81 R107.1 ; R138.1 153.94,188.8 ; 125.8,150.19 R35.1 ; 154.5,146.42 R134.1 154.69,146.3 ; 125.8,238.19 R59.1 ; 125.8,200.19 R47.1 ; 195.97,209.8 C107.1 195.6,209.8 ; 155.81,146.3 R135.1 156.19,146.3 ; 195.6,159.8 C119.1 195.97,159.8 ; 157.31,146.3 R136.1 157.69,146.3 ; 158.44,188.8 R141.1 158.06,188.8 ; 124.39,243.2 C77.1 124.03,243.2 ; 156.56,188.8 R140.1 156.94,188.8 ; 156.69,134.7 C164.1 ; 194.2,214.81 R83.1 ; C160.1 179.2,53.58 ; 158.81,146.3 R137.1 ; 195.97,121.8 C139.1 195.6,121.8 ; 125.8,112.19 R23.1 ; C13.1 152.76,73.75 ; 194.2,252.81 R71.1 ; 156.69,179.7 C165.1
+5V_DC_PRI: length 19.6
  TOP w0.3: v1(128.75,63.75) 130,65 130,66.76
  TOP w0.8: C11.1 130,66.76
  BOTTOM w0.2: 127,63.75 D5.K 127,65.05
  BOTTOM w0.5: 126.7,56.77 126.7,57.25 126.6,57.35 126.6,58.23 ; IC2.1 129.06,63.94 v1(128.75,63.75) 127,63.75 126.6,63.35 126.6,59.02 ; PS1.7 126.38,54.88 126.7,55.2 126.7,56.33
  BOTTOM w0.8: 126.7,56.77 C16.1 126.7,56.33 ; 126.6,59.02 R19.1 126.6,58.23
+5V_DC_SEC: length 19.1
  TOP w0.3: v1(191.5,46.5) 191.5,44.8 C155.1
  BOTTOM w0.2: 193,45.2 D56.K 193,46.5
  BOTTOM w0.5: 189.43,46.31 191.19,46.31 v1(191.5,46.5) 193,46.5 193.4,46.9 193.4,51.48 ; 193.3,53.48 193.3,53 193.4,52.9 193.4,52.25 ; PS10.7 194.12,54.57 C161.1
  BOTTOM w0.8: 193.4,52.25 R132.1 193.4,51.48 ; 193.3,53.48 C161.1
  BOTTOM w1.5: IC20.1 189.43,46.31
+12V_Q5: length 28.9
  TOP w0.2: TP22.1 216.6,246.9
  TOP w0.5: 220.18,258.5 219.31,258.5 ; 218.78,258.5 v2(217.75,258.5) ; 220.45,257.27 220.45,258.23
  TOP w0.6: v2(211.44,249.26) v2(213,249.26)
  TOP w0.7: 219.31,258.5 218.78,258.5
  TOP w0.8: C85.1 220.45,257.27 ; 220.18,258.5 R68.1 220.45,258.23
  CONDUCTIVE5 w0.5: v2(211.44,249.26) v2(213,249.26) 215.25,251.51 215.25,256 v2(217.75,258.5)
  BOTTOM w0.6: R78.1 213.3,248.74 v2(213,249.26) v2(211.44,249.26) ; v2(211.44,249.26) 211.44,248.46 R77.1 ; v2(211.44,249.26) C88.1 ; v2(211.44,249.26) 210.67,248.48 210.5,248.03 ; IC12.13 209.75,250.37 209.91,250.2 210.4,250.2
  BOTTOM w0.8: 210.4,250.2 C88.1 ; C89.1 210.5,248.03
